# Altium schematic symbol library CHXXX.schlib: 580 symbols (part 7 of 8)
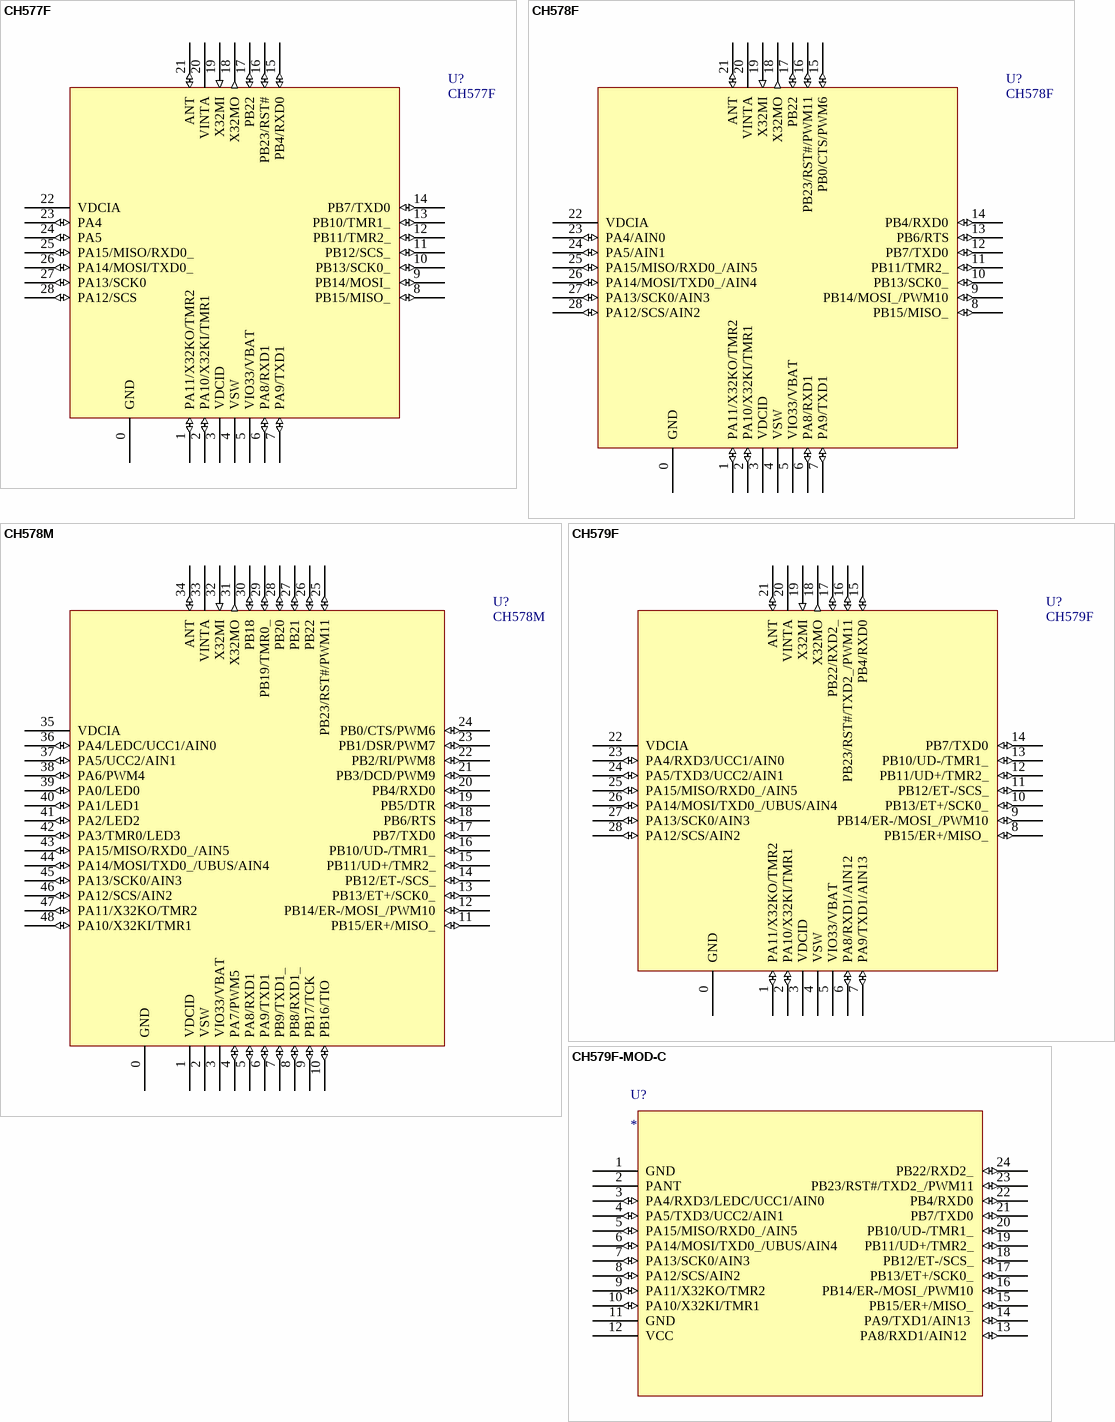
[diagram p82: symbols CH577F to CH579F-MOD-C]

## CH579F-MOD-C
designator U?
CH579F module, ARM M0 MCU with BLE+Ethernet+USB Host/Device
footprint BLEMOD-R2-1v0-24PIN
pins: 1 GND (power), 2 PANT, 3 PA4/RXD3/LEDC/UCC1/AIN0  (io), 4 PA5/TXD3/UCC2/AIN1   (io), 5 PA15/MISO/RXD0_/AIN5   (io), 6 PA14/MOSI/TXD0_/UBUS/AIN4 (io), 7 PA13/SCK0/AIN3   (io), 8 PA12/SCS/AIN2   (io), 9 PA11/X32KO/TMR2   (io), 10 PA10/X32KI/TMR1   (io), 11 GND (power), 12 VCC (power), 13 PA8/RXD1/AIN12   (io), 14 PA9/TXD1/AIN13  (io), 15 PB15/ER+/MISO_ (io), 16 PB14/ER-/MOSI_/PWM10 (io), 17 PB13/ET+/SCK0_ (io), 18 PB12/ET-/SCS_ (io), 19 PB11/UD+/TMR2_ (io), 20 PB10/UD-/TMR1_ (io), 21 PB7/TXD0 (io), 22 PB4/RXD0 (io), 23 PB23/RST#/TXD2_/PWM11 (io), 24 PB22/RXD2_ (io)

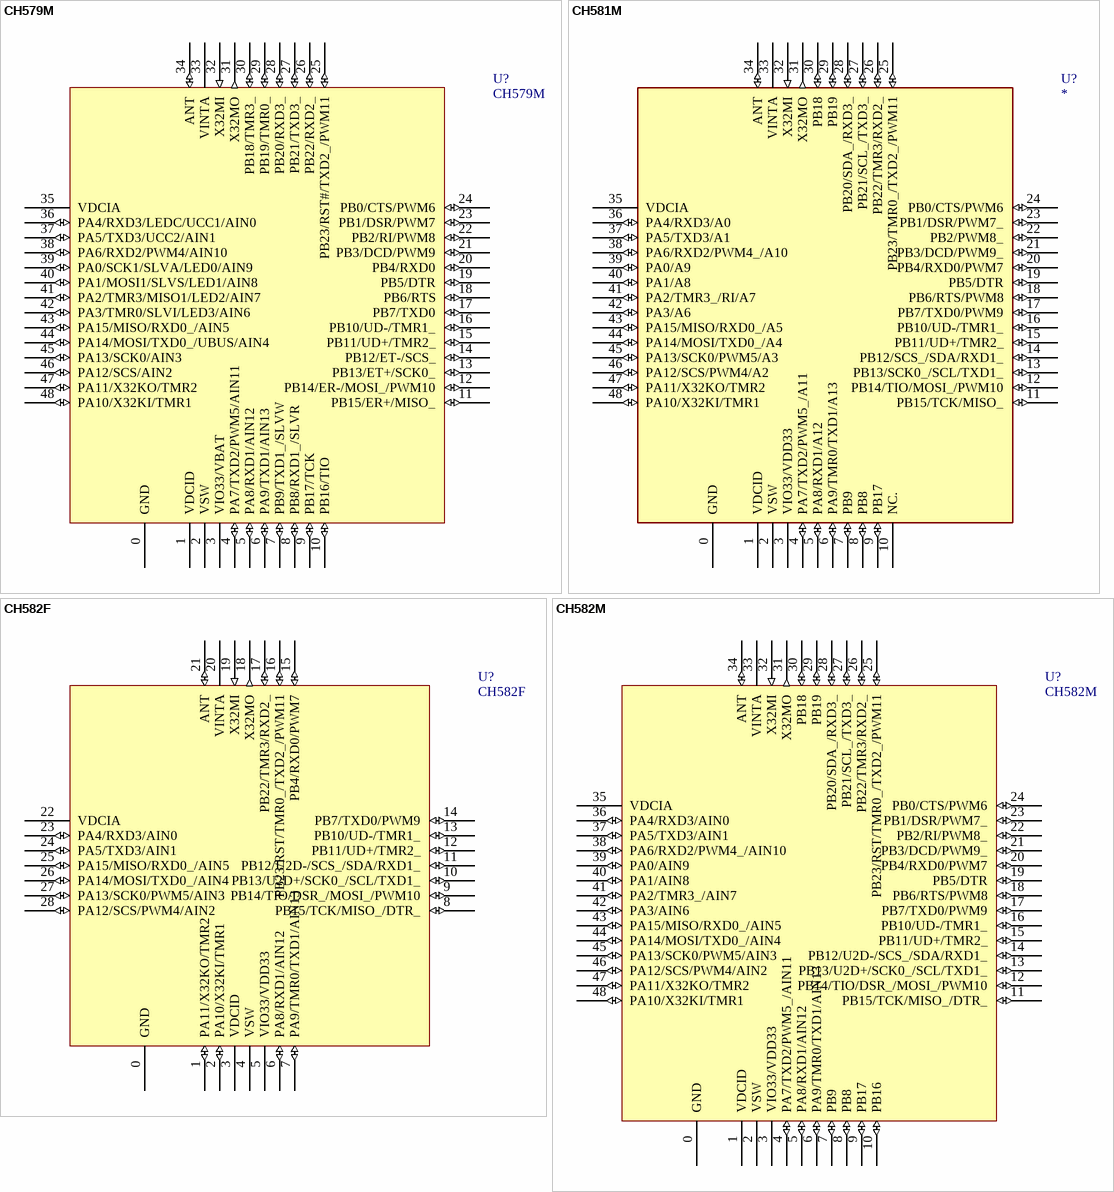
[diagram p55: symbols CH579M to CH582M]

## CH579M
designator U?
ARM M0 MCU with Bluetooth-LowEnergy+Ethernet+USB+segment-LCD
footprint QFN48_5X5
pins: 0 GND (power), 1 VDCID (power), 2 VSW (power), 3 VIO33/VBAT (power), 4 PA7/TXD2/PWM5/AIN11 (io), 5 PA8/RXD1/AIN12 (io), 6 PA9/TXD1/AIN13 (io), 7 PB9/TXD1_/SLVW (io), 8 PB8/RXD1_/SLVR (io), 9 PB17/TCK (io), 10 PB16/TIO (io), 11 PB15/ER+/MISO_ (io), 12 PB14/ER-/MOSI_/PWM10 (io), 13 PB13/ET+/SCK0_ (io), 14 PB12/ET-/SCS_ (io), 15 PB11/UD+/TMR2_ (io), 16 PB10/UD-/TMR1_ (io), 17 PB7/TXD0 (io), 18 PB6/RTS (io), 19 PB5/DTR (io), 20 PB4/RXD0 (io), 21 PB3/DCD/PWM9 (io), 22 PB2/RI/PWM8 (io), 23 PB1/DSR/PWM7 (io), 24 PB0/CTS/PWM6 (io), 25 PB23/RST#/TXD2_/PWM11 (io), 26 PB22/RXD2_ (io), 27 PB21/TXD3_ (io), 28 PB20/RXD3_ (io), 29 PB19/TMR0_ (io), 30 PB18/TMR3_ (io), 31 X32MO (out), 32 X32MI (in), 33 VINTA (power), 34 ANT (io), 35 VDCIA (power), 36 PA4/RXD3/LEDC/UCC1/AIN0 (io), 37 PA5/TXD3/UCC2/AIN1 (io), 38 PA6/RXD2/PWM4/AIN10 (io), 39 PA0/SCK1/SLVA/LED0/AIN9 (io), 40 PA1/MOSI1/SLVS/LED1/AIN8 (io), 41 PA2/TMR3/MISO1/LED2/AIN7 (io), 42 PA3/TMR0/SLVI/LED3/AIN6 (io), 43 PA15/MISO/RXD0_/AIN5 (io), 44 PA14/MOSI/TXD0_/UBUS/AIN4 (io), 45 PA13/SCK0/AIN3 (io), 46 PA12/SCS/AIN2 (io), 47 PA11/X32KO/TMR2 (io), 48 PA10/X32KI/TMR1 (io)

## CH581M
designator U?
RISC-V MCU with BLE/USB/ADC/PWM/SPI/I2C/4*UART
footprint QFN48_5X5
pins: 0 GND (power), 1 VDCID (power), 2 VSW (power), 3 VIO33/VDD33 (power), 4 PA7/TXD2/PWM5_/A11 (io), 5 PA8/RXD1/A12 (io), 6 PA9/TMR0/TXD1/A13 (io), 7 PB9 (io), 8 PB8 (io), 9 PB17 (io), 10 NC., 11 PB15/TCK/MISO_ (io), 12 PB14/TIO/MOSI_/PWM10 (io), 13 PB13/SCK0_/SCL/TXD1_ (io), 14 PB12/SCS_/SDA/RXD1_ (io), 15 PB11/UD+/TMR2_ (io), 16 PB10/UD-/TMR1_ (io), 17 PB7/TXD0/PWM9 (io), 18 PB6/RTS/PWM8 (io), 19 PB5/DTR (io), 20 PB4/RXD0/PWM7 (io), 21 PB3/DCD/PWM9_ (io), 22 PB2/PWM8_ (io), 23 PB1/DSR/PWM7_ (io), 24 PB0/CTS/PWM6 (io), 25 PB23/TMR0_/TXD2_/PWM11 (io), 26 PB22/TMR3/RXD2_ (io), 27 PB21/SCL_/TXD3_ (io), 28 PB20/SDA_/RXD3_ (io), 29 PB19 (io), 30 PB18 (io), 31 X32MO (out), 32 X32MI (in), 33 VINTA (power), 34 ANT (io), 35 VDCIA (power), 36 PA4/RXD3/A0 (io), 37 PA5/TXD3/A1 (io), 38 PA6/RXD2/PWM4_/A10 (io), 39 PA0/A9 (io), 40 PA1/A8 (io), 41 PA2/TMR3_/RI/A7 (io), 42 PA3/A6 (io), 43 PA15/MISO/RXD0_/A5 (io), 44 PA14/MOSI/TXD0_/A4 (io), 45 PA13/SCK0/PWM5/A3 (io), 46 PA12/SCS/PWM4/A2 (io), 47 PA11/X32KO/TMR2 (io), 48 PA10/X32KI/TMR1 (io)

## CH582F
designator U?
RISC-V MCU with BLE/2*USB/ADC/PWM/SPI/I2C/4*UART
footprint QFN28_4X4
pins: 0 GND (power), 1 PA11/X32KO/TMR2 (io), 2 PA10/X32KI/TMR1 (io), 3 VDCID (power), 4 VSW (power), 5 VIO33/VDD33 (power), 6 PA8/RXD1/AIN12 (io), 7 PA9/TMR0/TXD1/AIN13 (io), 8 PB15/TCK/MISO_/DTR_ (io), 9 PB14/TIO/DSR_/MOSI_/PWM10 (io), 10 PB13/U2D+/SCK0_/SCL/TXD1_ (io), 11 PB12/U2D-/SCS_/SDA/RXD1_ (io), 12 PB11/UD+/TMR2_ (io), 13 PB10/UD-/TMR1_ (io), 14 PB7/TXD0/PWM9 (io), 15 PB4/RXD0/PWM7 (io), 16 PB23/RST/TMR0_/TXD2_/PWM11 (io), 17 PB22/TMR3/RXD2_ (io), 18 X32MO (out), 19 X32MI (in), 20 VINTA (power), 21 ANT (io), 22 VDCIA (power), 23 PA4/RXD3/AIN0 (io), 24 PA5/TXD3/AIN1 (io), 25 PA15/MISO/RXD0_/AIN5 (io), 26 PA14/MOSI/TXD0_/AIN4 (io), 27 PA13/SCK0/PWM5/AIN3 (io), 28 PA12/SCS/PWM4/AIN2 (io)

## CH582M
designator U?
RISC-V MCU with BLE/2*USB/ADC/PWM/SPI/I2C/4*UART
footprint QFN48_5X5
pins: 0 GND (power), 1 VDCID (power), 2 VSW (power), 3 VIO33/VDD33 (power), 4 PA7/TXD2/PWM5_/AIN11 (io), 5 PA8/RXD1/AIN12 (io), 6 PA9/TMR0/TXD1/AIN13 (io), 7 PB9 (io), 8 PB8 (io), 9 PB17 (io), 10 PB16 (io), 11 PB15/TCK/MISO_/DTR_ (io), 12 PB14/TIO/DSR_/MOSI_/PWM10 (io), 13 PB13/U2D+/SCK0_/SCL/TXD1_ (io), 14 PB12/U2D-/SCS_/SDA/RXD1_ (io), 15 PB11/UD+/TMR2_ (io), 16 PB10/UD-/TMR1_ (io), 17 PB7/TXD0/PWM9 (io), 18 PB6/RTS/PWM8 (io), 19 PB5/DTR (io), 20 PB4/RXD0/PWM7 (io), 21 PB3/DCD/PWM9_ (io), 22 PB2/RI/PWM8_ (io), 23 PB1/DSR/PWM7_ (io), 24 PB0/CTS/PWM6 (io), 25 PB23/RST/TMR0_/TXD2_/PWM11 (io), 26 PB22/TMR3/RXD2_ (io), 27 PB21/SCL_/TXD3_ (io), 28 PB20/SDA_/RXD3_ (io), 29 PB19 (io), 30 PB18 (io), 31 X32MO (out), 32 X32MI (in), 33 VINTA (power), 34 ANT (io), 35 VDCIA (power), 36 PA4/RXD3/AIN0 (io), 37 PA5/TXD3/AIN1 (io), 38 PA6/RXD2/PWM4_/AIN10 (io), 39 PA0/AIN9 (io), 40 PA1/AIN8 (io), 41 PA2/TMR3_/AIN7 (io), 42 PA3/AIN6 (io), 43 PA15/MISO/RXD0_/AIN5 (io), 44 PA14/MOSI/TXD0_/AIN4 (io), 45 PA13/SCK0/PWM5/AIN3 (io), 46 PA12/SCS/PWM4/AIN2 (io), 47 PA11/X32KO/TMR2 (io), 48 PA10/X32KI/TMR1 (io)

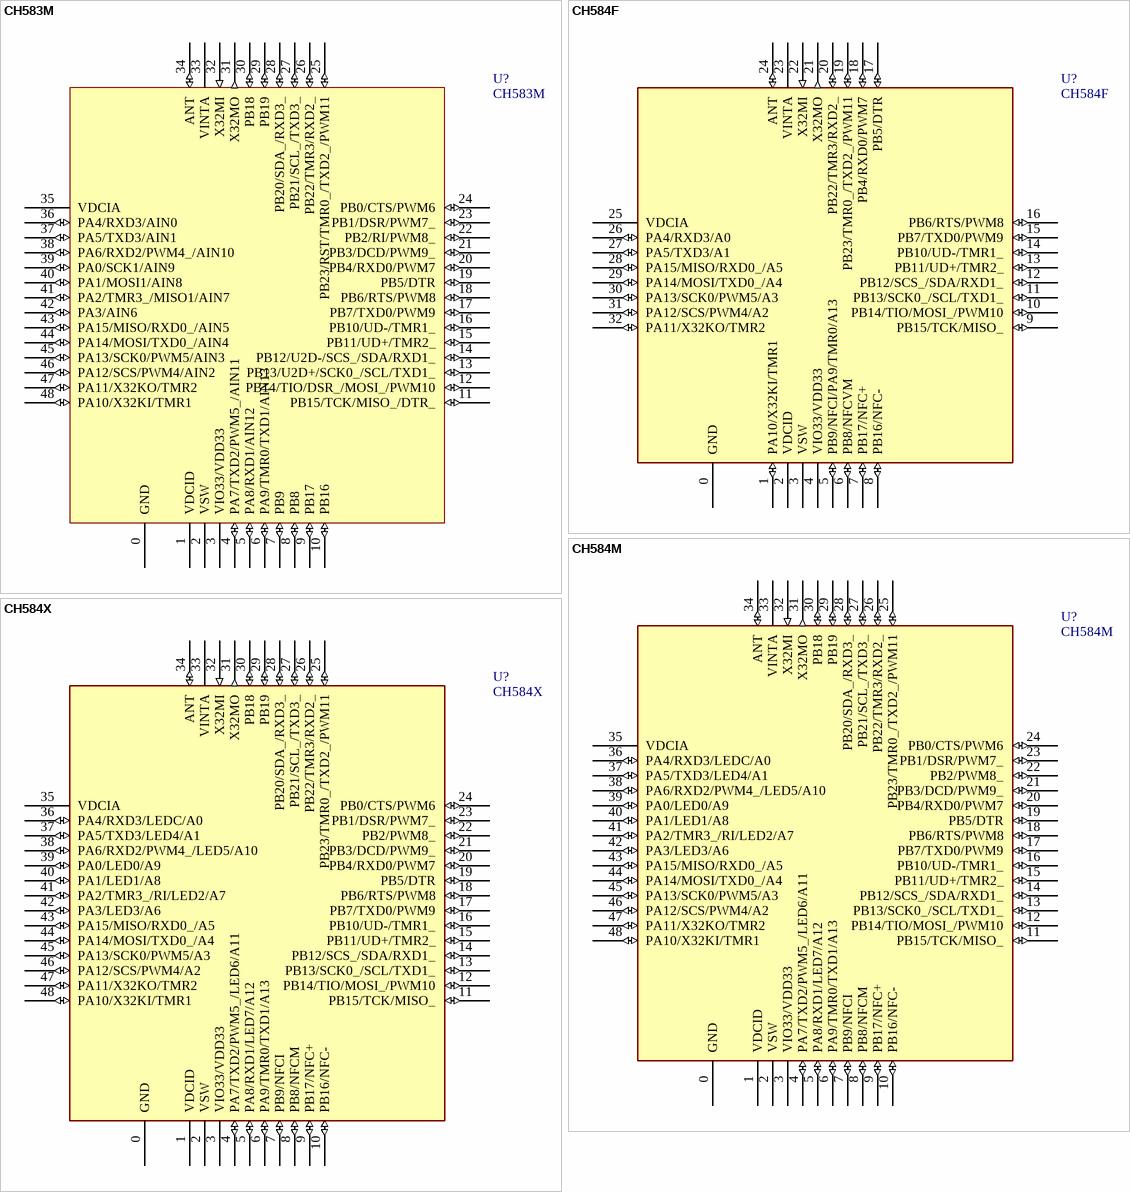
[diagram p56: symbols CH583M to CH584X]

## CH583M
designator U?
RISC-V MCU with BLE/2*USB/ADC/PWM/SPI/I2C/4*UART
footprint QFN48_5X5
pins: 0 GND (power), 1 VDCID (power), 2 VSW (power), 3 VIO33/VDD33 (power), 4 PA7/TXD2/PWM5_/AIN11 (io), 5 PA8/RXD1/AIN12 (io), 6 PA9/TMR0/TXD1/AIN13 (io), 7 PB9 (io), 8 PB8 (io), 9 PB17 (io), 10 PB16 (io), 11 PB15/TCK/MISO_/DTR_ (io), 12 PB14/TIO/DSR_/MOSI_/PWM10 (io), 13 PB13/U2D+/SCK0_/SCL/TXD1_ (io), 14 PB12/U2D-/SCS_/SDA/RXD1_ (io), 15 PB11/UD+/TMR2_ (io), 16 PB10/UD-/TMR1_ (io), 17 PB7/TXD0/PWM9 (io), 18 PB6/RTS/PWM8 (io), 19 PB5/DTR (io), 20 PB4/RXD0/PWM7 (io), 21 PB3/DCD/PWM9_ (io), 22 PB2/RI/PWM8_ (io), 23 PB1/DSR/PWM7_ (io), 24 PB0/CTS/PWM6 (io), 25 PB23/RST/TMR0_/TXD2_/PWM11 (io), 26 PB22/TMR3/RXD2_ (io), 27 PB21/SCL_/TXD3_ (io), 28 PB20/SDA_/RXD3_ (io), 29 PB19 (io), 30 PB18 (io), 31 X32MO (out), 32 X32MI (in), 33 VINTA (power), 34 ANT (io), 35 VDCIA (power), 36 PA4/RXD3/AIN0 (io), 37 PA5/TXD3/AIN1 (io), 38 PA6/RXD2/PWM4_/AIN10 (io), 39 PA0/SCK1/AIN9 (io), 40 PA1/MOSI1/AIN8 (io), 41 PA2/TMR3_/MISO1/AIN7 (io), 42 PA3/AIN6 (io), 43 PA15/MISO/RXD0_/AIN5 (io), 44 PA14/MOSI/TXD0_/AIN4 (io), 45 PA13/SCK0/PWM5/AIN3 (io), 46 PA12/SCS/PWM4/AIN2 (io), 47 PA11/X32KO/TMR2 (io), 48 PA10/X32KI/TMR1 (io)

## CH584F
designator U?
RISC-V MCU with BLE/USB/NFC/ADC/PWM/SPI/I2C/4*UART/LCD
footprint QFN32_4X4
pins: 0 GND (power), 1 PA10/X32KI/TMR1 (io), 2 VDCID (power), 3 VSW (power), 4 VIO33/VDD33 (power), 5 PB9/NFCI/PA9/TMR0/A13 (io), 6 PB8/NFCVM (io), 7 PB17/NFC+ (io), 8 PB16/NFC- (io), 9 PB15/TCK/MISO_ (io), 10 PB14/TIO/MOSI_/PWM10 (io), 11 PB13/SCK0_/SCL/TXD1_ (io), 12 PB12/SCS_/SDA/RXD1_ (io), 13 PB11/UD+/TMR2_ (io), 14 PB10/UD-/TMR1_ (io), 15 PB7/TXD0/PWM9 (io), 16 PB6/RTS/PWM8 (io), 17 PB5/DTR (io), 18 PB4/RXD0/PWM7 (io), 19 PB23/TMR0_/TXD2_/PWM11 (io), 20 PB22/TMR3/RXD2_ (io), 21 X32MO (out), 22 X32MI (in), 23 VINTA (power), 24 ANT (io), 25 VDCIA (power), 26 PA4/RXD3/A0 (io), 27 PA5/TXD3/A1 (io), 28 PA15/MISO/RXD0_/A5 (io), 29 PA14/MOSI/TXD0_/A4 (io), 30 PA13/SCK0/PWM5/A3 (io), 31 PA12/SCS/PWM4/A2 (io), 32 PA11/X32KO/TMR2 (io)

## CH584M
designator U?
RISC-V MCU with BLE/USB/NFC/ADC/PWM/SPI/I2C/4*UART/LCD
footprint QFN48_5X5
pins: 0 GND (power), 1 VDCID (power), 2 VSW (power), 3 VIO33/VDD33 (power), 4 PA7/TXD2/PWM5_/LED6/A11 (io), 5 PA8/RXD1/LED7/A12 (io), 6 PA9/TMR0/TXD1/A13 (io), 7 PB9/NFCI (io), 8 PB8/NFCM (io), 9 PB17/NFC+ (io), 10 PB16/NFC- (io), 11 PB15/TCK/MISO_ (io), 12 PB14/TIO/MOSI_/PWM10 (io), 13 PB13/SCK0_/SCL/TXD1_ (io), 14 PB12/SCS_/SDA/RXD1_ (io), 15 PB11/UD+/TMR2_ (io), 16 PB10/UD-/TMR1_ (io), 17 PB7/TXD0/PWM9 (io), 18 PB6/RTS/PWM8 (io), 19 PB5/DTR (io), 20 PB4/RXD0/PWM7 (io), 21 PB3/DCD/PWM9_ (io), 22 PB2/PWM8_ (io), 23 PB1/DSR/PWM7_ (io), 24 PB0/CTS/PWM6 (io), 25 PB23/TMR0_/TXD2_/PWM11 (io), 26 PB22/TMR3/RXD2_ (io), 27 PB21/SCL_/TXD3_ (io), 28 PB20/SDA_/RXD3_ (io), 29 PB19 (io), 30 PB18 (io), 31 X32MO (out), 32 X32MI (in), 33 VINTA (power), 34 ANT (io), 35 VDCIA (power), 36 PA4/RXD3/LEDC/A0 (io), 37 PA5/TXD3/LED4/A1 (io), 38 PA6/RXD2/PWM4_/LED5/A10 (io), 39 PA0/LED0/A9 (io), 40 PA1/LED1/A8 (io), 41 PA2/TMR3_/RI/LED2/A7 (io), 42 PA3/LED3/A6 (io), 43 PA15/MISO/RXD0_/A5 (io), 44 PA14/MOSI/TXD0_/A4 (io), 45 PA13/SCK0/PWM5/A3 (io), 46 PA12/SCS/PWM4/A2 (io), 47 PA11/X32KO/TMR2 (io), 48 PA10/X32KI/TMR1 (io)

## CH584X
designator U?
RISC-V MCU with BLE/USB/NFC/ADC/PWM/SPI/I2C/4*UART/LCD
footprint QFN48_5X5
pins: 0 GND (power), 1 VDCID (power), 2 VSW (power), 3 VIO33/VDD33 (power), 4 PA7/TXD2/PWM5_/LED6/A11 (io), 5 PA8/RXD1/LED7/A12 (io), 6 PA9/TMR0/TXD1/A13 (io), 7 PB9/NFCI (io), 8 PB8/NFCM (io), 9 PB17/NFC+ (io), 10 PB16/NFC- (io), 11 PB15/TCK/MISO_ (io), 12 PB14/TIO/MOSI_/PWM10 (io), 13 PB13/SCK0_/SCL/TXD1_ (io), 14 PB12/SCS_/SDA/RXD1_ (io), 15 PB11/UD+/TMR2_ (io), 16 PB10/UD-/TMR1_ (io), 17 PB7/TXD0/PWM9 (io), 18 PB6/RTS/PWM8 (io), 19 PB5/DTR (io), 20 PB4/RXD0/PWM7 (io), 21 PB3/DCD/PWM9_ (io), 22 PB2/PWM8_ (io), 23 PB1/DSR/PWM7_ (io), 24 PB0/CTS/PWM6 (io), 25 PB23/TMR0_/TXD2_/PWM11 (io), 26 PB22/TMR3/RXD2_ (io), 27 PB21/SCL_/TXD3_ (io), 28 PB20/SDA_/RXD3_ (io), 29 PB19 (io), 30 PB18 (io), 31 X32MO (out), 32 X32MI (in), 33 VINTA (power), 34 ANT (io), 35 VDCIA (power), 36 PA4/RXD3/LEDC/A0 (io), 37 PA5/TXD3/LED4/A1 (io), 38 PA6/RXD2/PWM4_/LED5/A10 (io), 39 PA0/LED0/A9 (io), 40 PA1/LED1/A8 (io), 41 PA2/TMR3_/RI/LED2/A7 (io), 42 PA3/LED3/A6 (io), 43 PA15/MISO/RXD0_/A5 (io), 44 PA14/MOSI/TXD0_/A4 (io), 45 PA13/SCK0/PWM5/A3 (io), 46 PA12/SCS/PWM4/A2 (io), 47 PA11/X32KO/TMR2 (io), 48 PA10/X32KI/TMR1 (io)

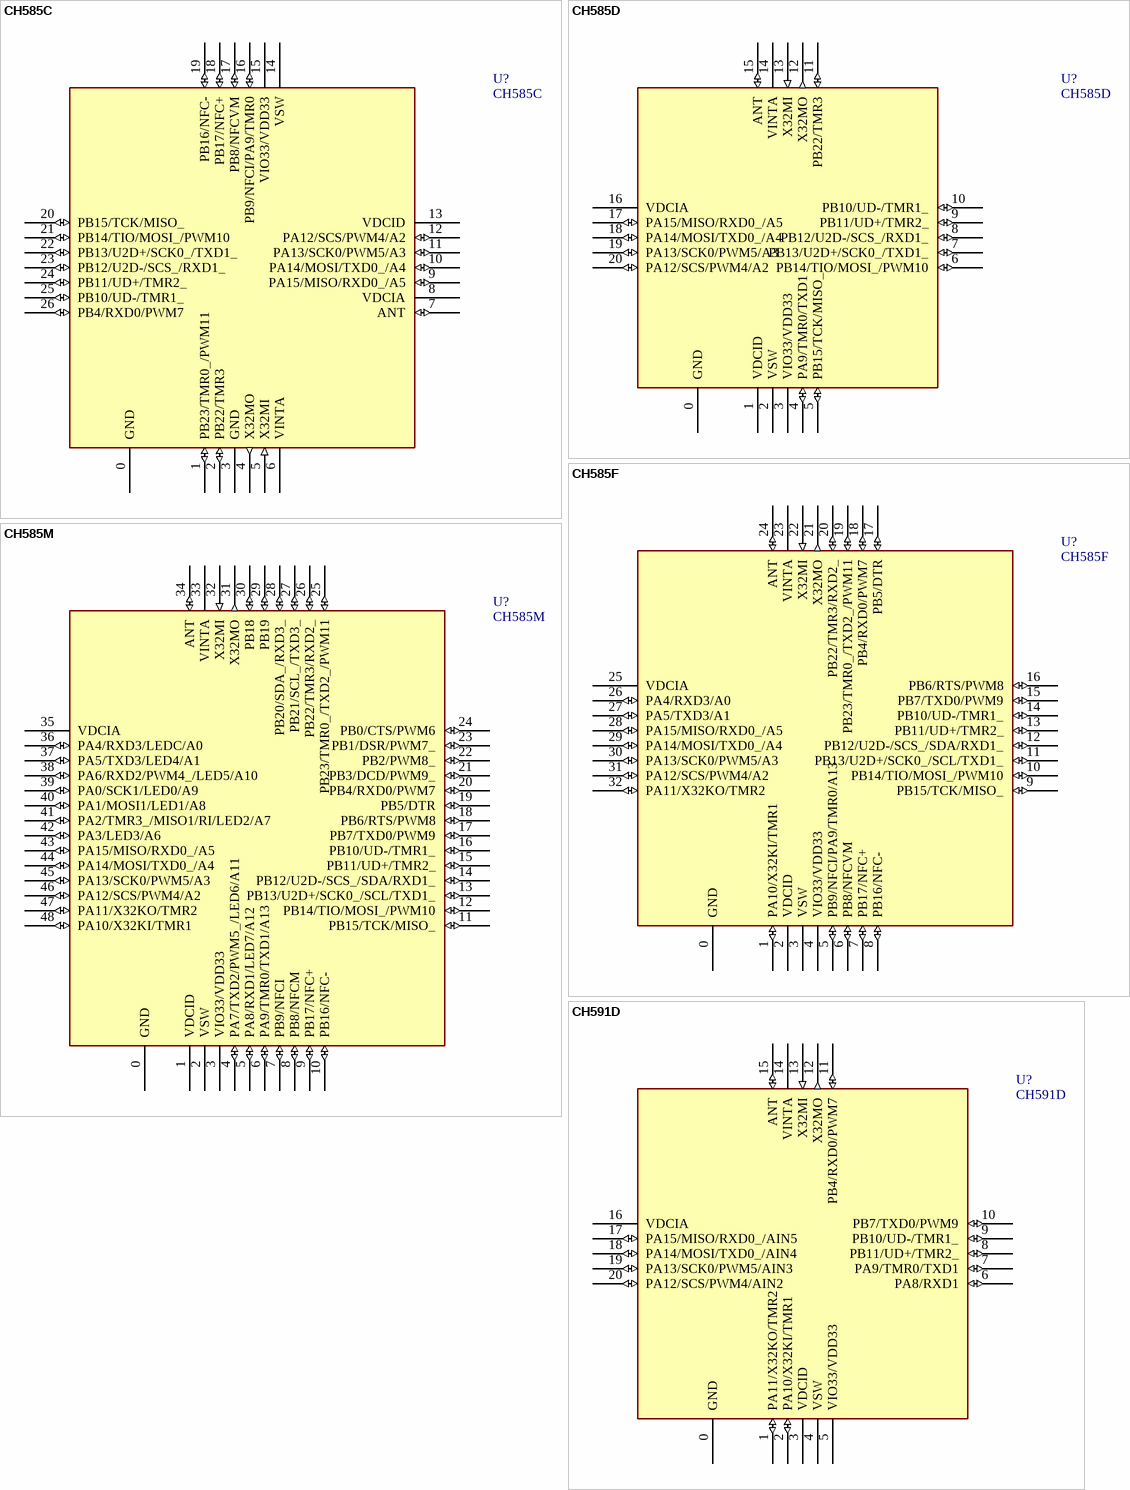
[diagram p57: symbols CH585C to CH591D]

## CH585C
designator U?
RISC-V MCU with BLE/HSUSB/USB/NFC/ADC/PWM/SPI/2*UART
footprint QFN26C_3X3
pins: 0 GND (power), 1 PB23/TMR0_/PWM11 (io), 2 PB22/TMR3 (io), 3 GND (power), 4 X32MO (out), 5 X32MI (in), 6 VINTA (power), 7 ANT (io), 8 VDCIA (power), 9 PA15/MISO/RXD0_/A5 (io), 10 PA14/MOSI/TXD0_/A4 (io), 11 PA13/SCK0/PWM5/A3 (io), 12 PA12/SCS/PWM4/A2 (io), 13 VDCID (power), 14 VSW (power), 15 VIO33/VDD33 (power), 16 PB9/NFCI/PA9/TMR0 (io), 17 PB8/NFCVM (io), 18 PB17/NFC+ (io), 19 PB16/NFC- (io), 20 PB15/TCK/MISO_ (io), 21 PB14/TIO/MOSI_/PWM10 (io), 22 PB13/U2D+/SCK0_/TXD1_ (io), 23 PB12/U2D-/SCS_/RXD1_ (io), 24 PB11/UD+/TMR2_ (io), 25 PB10/UD-/TMR1_ (io), 26 PB4/RXD0/PWM7 (io)

## CH585D
designator U?
RISC-V MCU with BLE/HSUSB/USB/ADC/PWM/SPI/2*UART
footprint QFN20_3X3 (Footprint not found)
pins: 0 GND (power), 1 VDCID (power), 2 VSW (power), 3 VIO33/VDD33 (power), 4 PA9/TMR0/TXD1 (io), 5 PB15/TCK/MISO_ (io), 6 PB14/TIO/MOSI_/PWM10 (io), 7 PB13/U2D+/SCK0_/TXD1_ (io), 8 PB12/U2D-/SCS_/RXD1_ (io), 9 PB11/UD+/TMR2_ (io), 10 PB10/UD-/TMR1_ (io), 11 PB22/TMR3 (io), 12 X32MO (out), 13 X32MI (in), 14 VINTA (power), 15 ANT (io), 16 VDCIA (power), 17 PA15/MISO/RXD0_/A5 (io), 18 PA14/MOSI/TXD0_/A4 (io), 19 PA13/SCK0/PWM5/A3 (io), 20 PA12/SCS/PWM4/A2 (io)

## CH585F
designator U?
RISC-V MCU with BLE/HSUSB/USB/NFC/ADC/PWM/SPI/I2C/4*UART/LCD
footprint QFN32_4X4
pins: 0 GND (power), 1 PA10/X32KI/TMR1 (io), 2 VDCID (power), 3 VSW (power), 4 VIO33/VDD33 (power), 5 PB9/NFCI/PA9/TMR0/A13 (io), 6 PB8/NFCVM (io), 7 PB17/NFC+ (io), 8 PB16/NFC- (io), 9 PB15/TCK/MISO_ (io), 10 PB14/TIO/MOSI_/PWM10 (io), 11 PB13/U2D+/SCK0_/SCL/TXD1_ (io), 12 PB12/U2D-/SCS_/SDA/RXD1_ (io), 13 PB11/UD+/TMR2_ (io), 14 PB10/UD-/TMR1_ (io), 15 PB7/TXD0/PWM9 (io), 16 PB6/RTS/PWM8 (io), 17 PB5/DTR (io), 18 PB4/RXD0/PWM7 (io), 19 PB23/TMR0_/TXD2_/PWM11 (io), 20 PB22/TMR3/RXD2_ (io), 21 X32MO (out), 22 X32MI (in), 23 VINTA (power), 24 ANT (io), 25 VDCIA (power), 26 PA4/RXD3/A0 (io), 27 PA5/TXD3/A1 (io), 28 PA15/MISO/RXD0_/A5 (io), 29 PA14/MOSI/TXD0_/A4 (io), 30 PA13/SCK0/PWM5/A3 (io), 31 PA12/SCS/PWM4/A2 (io), 32 PA11/X32KO/TMR2 (io)

## CH585M
designator U?
RISC-V MCU with BLE/HSUSB/USB/NFC/ADC/PWM/2*SPI/I2C/4*UART/LCD
footprint QFN48_5X5
pins: 0 GND (power), 1 VDCID (power), 2 VSW (power), 3 VIO33/VDD33 (power), 4 PA7/TXD2/PWM5_/LED6/A11 (io), 5 PA8/RXD1/LED7/A12 (io), 6 PA9/TMR0/TXD1/A13 (io), 7 PB9/NFCI (io), 8 PB8/NFCM (io), 9 PB17/NFC+ (io), 10 PB16/NFC- (io), 11 PB15/TCK/MISO_ (io), 12 PB14/TIO/MOSI_/PWM10 (io), 13 PB13/U2D+/SCK0_/SCL/TXD1_ (io), 14 PB12/U2D-/SCS_/SDA/RXD1_ (io), 15 PB11/UD+/TMR2_ (io), 16 PB10/UD-/TMR1_ (io), 17 PB7/TXD0/PWM9 (io), 18 PB6/RTS/PWM8 (io), 19 PB5/DTR (io), 20 PB4/RXD0/PWM7 (io), 21 PB3/DCD/PWM9_ (io), 22 PB2/PWM8_ (io), 23 PB1/DSR/PWM7_ (io), 24 PB0/CTS/PWM6 (io), 25 PB23/TMR0_/TXD2_/PWM11 (io), 26 PB22/TMR3/RXD2_ (io), 27 PB21/SCL_/TXD3_ (io), 28 PB20/SDA_/RXD3_ (io), 29 PB19 (io), 30 PB18 (io), 31 X32MO (out), 32 X32MI (in), 33 VINTA (power), 34 ANT (io), 35 VDCIA (power), 36 PA4/RXD3/LEDC/A0 (io), 37 PA5/TXD3/LED4/A1 (io), 38 PA6/RXD2/PWM4_/LED5/A10 (io), 39 PA0/SCK1/LED0/A9 (io), 40 PA1/MOSI1/LED1/A8 (io), 41 PA2/TMR3_/MISO1/RI/LED2/A7 (io), 42 PA3/LED3/A6 (io), 43 PA15/MISO/RXD0_/A5 (io), 44 PA14/MOSI/TXD0_/A4 (io), 45 PA13/SCK0/PWM5/A3 (io), 46 PA12/SCS/PWM4/A2 (io), 47 PA11/X32KO/TMR2 (io), 48 PA10/X32KI/TMR1 (io)

## CH591D
designator U?
RISC-V MCU with BLE/USB/ADC/SPI/2*UART
footprint QFN20_3X3
pins: 0 GND (power), 1 PA11/X32KO/TMR2 (io), 2 PA10/X32KI/TMR1 (io), 3 VDCID (power), 4 VSW (power), 5 VIO33/VDD33 (power), 6 PA8/RXD1 (io), 7 PA9/TMR0/TXD1 (io), 8 PB11/UD+/TMR2_ (io), 9 PB10/UD-/TMR1_ (io), 10 PB7/TXD0/PWM9 (io), 11 PB4/RXD0/PWM7 (io), 12 X32MO (out), 13 X32MI (in), 14 VINTA (power), 15 ANT (io), 16 VDCIA (power), 17 PA15/MISO/RXD0_/AIN5 (io), 18 PA14/MOSI/TXD0_/AIN4 (io), 19 PA13/SCK0/PWM5/AIN3 (io), 20 PA12/SCS/PWM4/AIN2 (io)

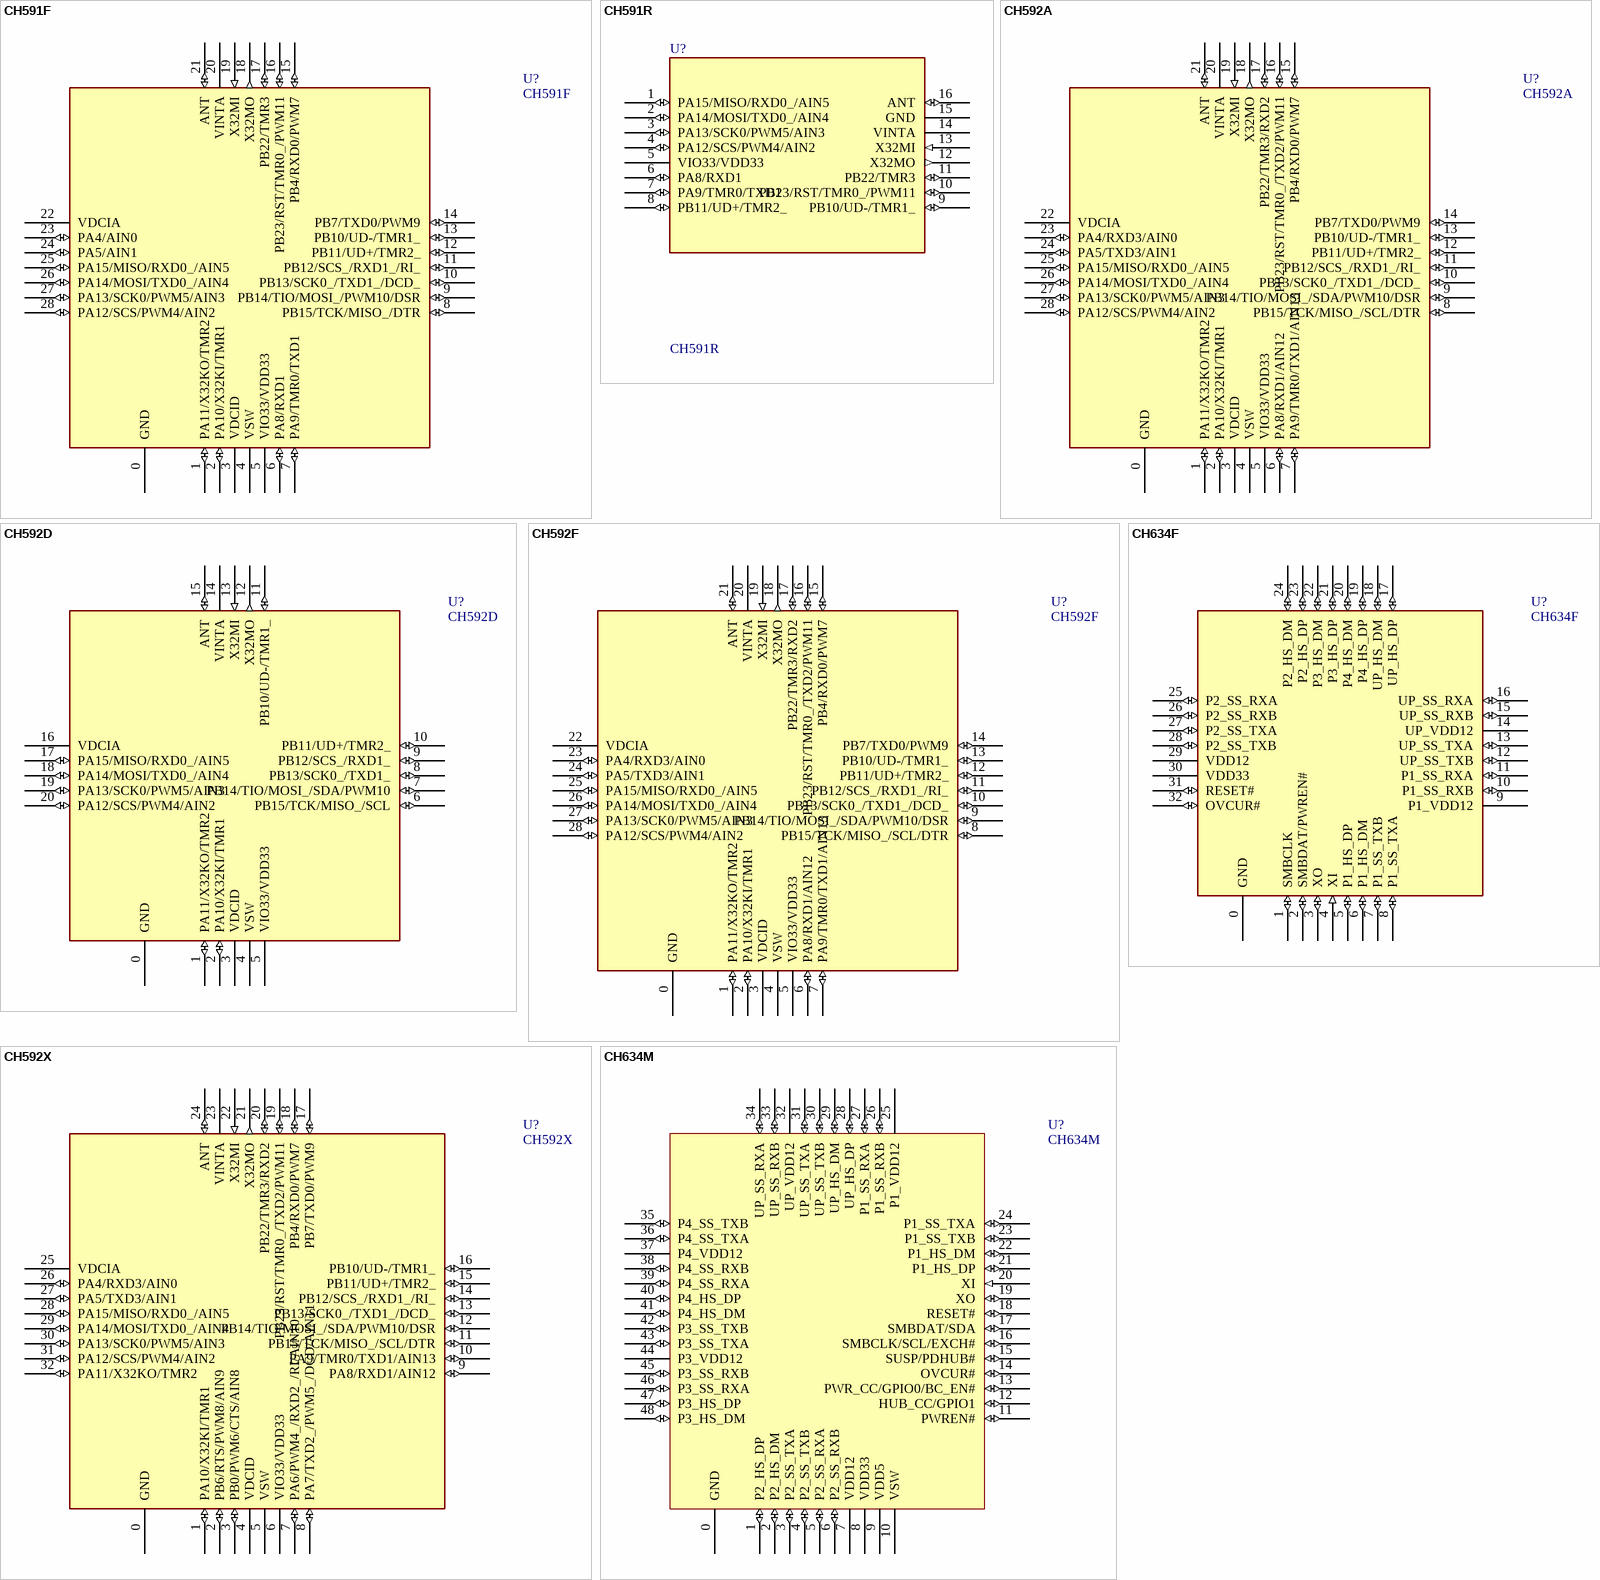
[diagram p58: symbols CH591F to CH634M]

## CH591F
designator U?
RISC-V MCU with BLE/USB/ADC/SPI/2*UART/LCD
footprint QFN28_4X4 (Footprint not found)
pins: 0 GND (power), 1 PA11/X32KO/TMR2 (io), 2 PA10/X32KI/TMR1 (io), 3 VDCID (power), 4 VSW (power), 5 VIO33/VDD33 (power), 6 PA8/RXD1 (io), 7 PA9/TMR0/TXD1 (io), 8 PB15/TCK/MISO_/DTR (io), 9 PB14/TIO/MOSI_/PWM10/DSR (io), 10 PB13/SCK0_/TXD1_/DCD_ (io), 11 PB12/SCS_/RXD1_/RI_ (io), 12 PB11/UD+/TMR2_ (io), 13 PB10/UD-/TMR1_ (io), 14 PB7/TXD0/PWM9 (io), 15 PB4/RXD0/PWM7 (io), 16 PB23/RST/TMR0_/PWM11 (io), 17 PB22/TMR3 (io), 18 X32MO (out), 19 X32MI (in), 20 VINTA (power), 21 ANT (io), 22 VDCIA (power), 23 PA4/AIN0 (io), 24 PA5/AIN1 (io), 25 PA15/MISO/RXD0_/AIN5 (io), 26 PA14/MOSI/TXD0_/AIN4 (io), 27 PA13/SCK0/PWM5/AIN3 (io), 28 PA12/SCS/PWM4/AIN2 (io)

## CH591R
designator U?
RISC-V MCU with BLE/USB/ADC/SPI/2*UART
footprint TSSOP16 (Footprint not found)
pins: 1 PA15/MISO/RXD0_/AIN5 (io), 2 PA14/MOSI/TXD0_/AIN4 (io), 3 PA13/SCK0/PWM5/AIN3 (io), 4 PA12/SCS/PWM4/AIN2 (io), 5 VIO33/VDD33 (power), 6 PA8/RXD1 (io), 7 PA9/TMR0/TXD1 (io), 8 PB11/UD+/TMR2_ (io), 9 PB10/UD-/TMR1_ (io), 10 PB23/RST/TMR0_/PWM11 (io), 11 PB22/TMR3 (io), 12 X32MO (out), 13 X32MI (in), 14 VINTA (power), 15 GND (power), 16 ANT (io)

## CH592A
designator U?
RISC-V MCU with BLE/USB/ADC/SPI/4*UART/I2C/LCD
footprint QFN28_4X4 (Footprint not found)
pins: 0 GND (power), 1 PA11/X32KO/TMR2 (io), 2 PA10/X32KI/TMR1 (io), 3 VDCID (power), 4 VSW (power), 5 VIO33/VDD33 (power), 6 PA8/RXD1/AIN12 (io), 7 PA9/TMR0/TXD1/AIN13 (io), 8 PB15/TCK/MISO_/SCL/DTR (io), 9 PB14/TIO/MOSI_/SDA/PWM10/DSR (io), 10 PB13/SCK0_/TXD1_/DCD_ (io), 11 PB12/SCS_/RXD1_/RI_ (io), 12 PB11/UD+/TMR2_ (io), 13 PB10/UD-/TMR1_ (io), 14 PB7/TXD0/PWM9 (io), 15 PB4/RXD0/PWM7 (io), 16 PB23/RST/TMR0_/TXD2/PWM11 (io), 17 PB22/TMR3/RXD2 (io), 18 X32MO (out), 19 X32MI (in), 20 VINTA (power), 21 ANT (io), 22 VDCIA (power), 23 PA4/RXD3/AIN0 (io), 24 PA5/TXD3/AIN1 (io), 25 PA15/MISO/RXD0_/AIN5 (io), 26 PA14/MOSI/TXD0_/AIN4 (io), 27 PA13/SCK0/PWM5/AIN3 (io), 28 PA12/SCS/PWM4/AIN2 (io)

## CH592D
designator U?
RISC-V MCU with BLE/USB/ADC/SPI/2*UART/I2C
footprint QFN20_3X3
pins: 0 GND (power), 1 PA11/X32KO/TMR2 (io), 2 PA10/X32KI/TMR1 (io), 3 VDCID (power), 4 VSW (power), 5 VIO33/VDD33 (power), 6 PB15/TCK/MISO_/SCL (io), 7 PB14/TIO/MOSI_/SDA/PWM10 (io), 8 PB13/SCK0_/TXD1_ (io), 9 PB12/SCS_/RXD1_ (io), 10 PB11/UD+/TMR2_ (io), 11 PB10/UD-/TMR1_ (io), 12 X32MO (out), 13 X32MI (in), 14 VINTA (power), 15 ANT (io), 16 VDCIA (power), 17 PA15/MISO/RXD0_/AIN5 (io), 18 PA14/MOSI/TXD0_/AIN4 (io), 19 PA13/SCK0/PWM5/AIN3 (io), 20 PA12/SCS/PWM4/AIN2 (io)

## CH592F
designator U?
RISC-V MCU with BLE/USB/ADC/SPI/4*UART/I2C/LCD
footprint QFN28_4X4 (Footprint not found)
pins: 0 GND (power), 1 PA11/X32KO/TMR2 (io), 2 PA10/X32KI/TMR1 (io), 3 VDCID (power), 4 VSW (power), 5 VIO33/VDD33 (power), 6 PA8/RXD1/AIN12 (io), 7 PA9/TMR0/TXD1/AIN13 (io), 8 PB15/TCK/MISO_/SCL/DTR (io), 9 PB14/TIO/MOSI_/SDA/PWM10/DSR (io), 10 PB13/SCK0_/TXD1_/DCD_ (io), 11 PB12/SCS_/RXD1_/RI_ (io), 12 PB11/UD+/TMR2_ (io), 13 PB10/UD-/TMR1_ (io), 14 PB7/TXD0/PWM9 (io), 15 PB4/RXD0/PWM7 (io), 16 PB23/RST/TMR0_/TXD2/PWM11 (io), 17 PB22/TMR3/RXD2 (io), 18 X32MO (out), 19 X32MI (in), 20 VINTA (power), 21 ANT (io), 22 VDCIA (power), 23 PA4/RXD3/AIN0 (io), 24 PA5/TXD3/AIN1 (io), 25 PA15/MISO/RXD0_/AIN5 (io), 26 PA14/MOSI/TXD0_/AIN4 (io), 27 PA13/SCK0/PWM5/AIN3 (io), 28 PA12/SCS/PWM4/AIN2 (io)

## CH592X
designator U?
RISC-V MCU with BLE/USB/ADC/SPI/4*UART/I2C/LCD
footprint QFN32_4X4
pins: 0 GND (power), 1 PA10/X32KI/TMR1 (io), 2 PB6/RTS/PWM8/AIN9 (io), 3 PB0/PWM6/CTS/AIN8 (io), 4 VDCID (power), 5 VSW (power), 6 VIO33/VDD33 (power), 7 PA6/PWM4_/RXD2_/RI/AIN10 (io), 8 PA7/TXD2_/PWM5_/DCD/AIN11 (io), 9 PA8/RXD1/AIN12 (io), 10 PA9/TMR0/TXD1/AIN13 (io), 11 PB15/TCK/MISO_/SCL/DTR (io), 12 PB14/TIO/MOSI_/SDA/PWM10/DSR (io), 13 PB13/SCK0_/TXD1_/DCD_ (io), 14 PB12/SCS_/RXD1_/RI_ (io), 15 PB11/UD+/TMR2_ (io), 16 PB10/UD-/TMR1_ (io), 17 PB7/TXD0/PWM9 (io), 18 PB4/RXD0/PWM7 (io), 19 PB23/RST/TMR0_/TXD2/PWM11 (io), 20 PB22/TMR3/RXD2 (io), 21 X32MO (out), 22 X32MI (in), 23 VINTA (power), 24 ANT (io), 25 VDCIA (power), 26 PA4/RXD3/AIN0 (io), 27 PA5/TXD3/AIN1 (io), 28 PA15/MISO/RXD0_/AIN5 (io), 29 PA14/MOSI/TXD0_/AIN4 (io), 30 PA13/SCK0/PWM5/AIN3 (io), 31 PA12/SCS/PWM4/AIN2 (io), 32 PA11/X32KO/TMR2 (io)

## CH634F
designator U?
2 ports USB 3.0 SS hub + 2 ports USB 2.0 HS hub
footprint QFN32_4X4
pins: 0 GND (power), 1 SMBCLK (io), 2 SMBDAT/PWREN# (io), 3 XO (io), 4 XI (in), 5 P1_HS_DP (io), 6 P1_HS_DM (io), 7 P1_SS_TXB (io), 8 P1_SS_TXA (io), 9 P1_VDD12 (power), 10 P1_SS_RXB (io), 11 P1_SS_RXA (io), 12 UP_SS_TXB (io), 13 UP_SS_TXA (io), 14 UP_VDD12 (power), 15 UP_SS_RXB (io), 16 UP_SS_RXA (io), 17 UP_HS_DP (io), 18 UP_HS_DM (io), 19 P4_HS_DP (io), 20 P4_HS_DM (io), 21 P3_HS_DP (io), 22 P3_HS_DM (io), 23 P2_HS_DP (io), 24 P2_HS_DM (io), 25 P2_SS_RXA (io), 26 P2_SS_RXB (io), 27 P2_SS_TXA (io), 28 P2_SS_TXB (io), 29 VDD12 (power), 30 VDD33 (power), 31 RESET# (io), 32 OVCUR# (io)

## CH634M
designator U?
4 ports USB 3.0 SS hub
footprint QFN48_5X5
pins: 0 GND (power), 1 P2_HS_DP (io), 2 P2_HS_DM (io), 3 P2_SS_TXA (io), 4 P2_SS_TXB (io), 5 P2_SS_RXA (io), 6 P2_SS_RXB (io), 7 VDD12 (power), 8 VDD33 (power), 9 VDD5 (power), 10 VSW (power), 11 PWREN# (io), 12 HUB_CC/GPIO1 (io), 13 PWR_CC/GPIO0/BC_EN# (io), 14 OVCUR# (io), 15 SUSP/PDHUB# (io), 16 SMBCLK/SCL/EXCH# (io), 17 SMBDAT/SDA (io), 18 RESET# (io), 19 XO (io), 20 XI (in), 21 P1_HS_DP (io), 22 P1_HS_DM (io), 23 P1_SS_TXB (io), 24 P1_SS_TXA (io), 25 P1_VDD12 (power), 26 P1_SS_RXB (io), 27 P1_SS_RXA (io), 28 UP_HS_DP (io), 29 UP_HS_DM (io), 30 UP_SS_TXB (io), 31 UP_SS_TXA (io), 32 UP_VDD12 (power), 33 UP_SS_RXB (io), 34 UP_SS_RXA (io), 35 P4_SS_TXB (io), 36 P4_SS_TXA (io), 37 P4_VDD12 (power), 38 P4_SS_RXB (io), 39 P4_SS_RXA (io), 40 P4_HS_DP (io), 41 P4_HS_DM (io), 42 P3_SS_TXB (io), 43 P3_SS_TXA (io), 44 P3_VDD12 (power), 45 P3_SS_RXB (io), 46 P3_SS_RXA (io), 47 P3_HS_DP (io), 48 P3_HS_DM (io)

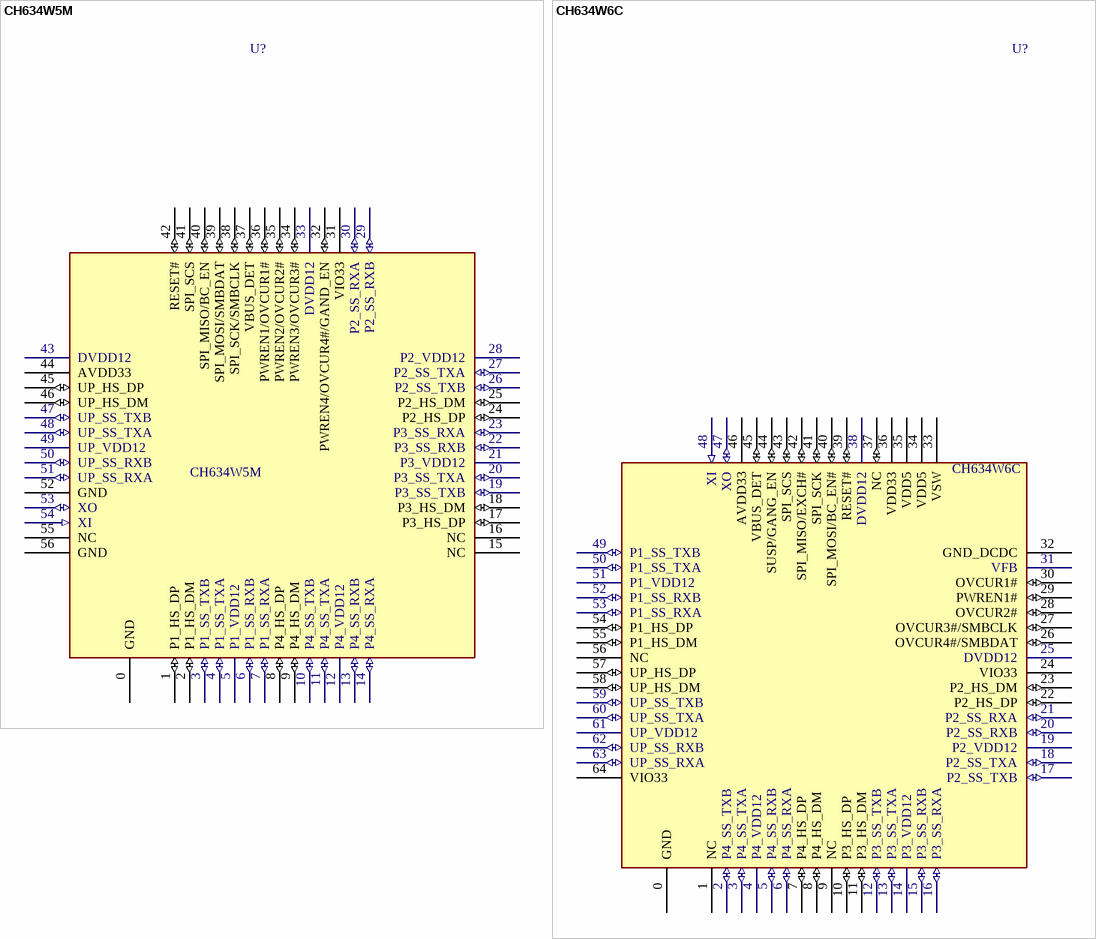
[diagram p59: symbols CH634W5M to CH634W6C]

## CH634W5M
designator U?
4 ports USB 3.0 SS hub
footprint QFN56_7x7
pins: 0 GND (power), 1 P1_HS_DP (io), 2 P1_HS_DM (io), 3 P1_SS_TXB (io), 4 P1_SS_TXA (io), 5 P1_VDD12 (power), 6 P1_SS_RXB (io), 7 P1_SS_RXA (io), 8 P4_HS_DP (io), 9 P4_HS_DM (io), 10 P4_SS_TXB (io), 11 P4_SS_TXA (io), 12 P4_VDD12 (power), 13 P4_SS_RXB (io), 14 P4_SS_RXA (io), 15 NC, 16 NC, 17 P3_HS_DP (io), 18 P3_HS_DM (io), 19 P3_SS_TXB (io), 20 P3_SS_TXA (io), 21 P3_VDD12 (power), 22 P3_SS_RXB (io), 23 P3_SS_RXA (io), 24 P2_HS_DP (io), 25 P2_HS_DM (io), 26 P2_SS_TXB (io), 27 P2_SS_TXA (io), 28 P2_VDD12 (power), 29 P2_SS_RXB (io), 30 P2_SS_RXA (io), 31 VIO33 (power), 32 PWREN4/OVCUR4#/GAND_EN (io), 33 DVDD12 (power), 34 PWREN3/OVCUR3# (io), 35 PWREN2/OVCUR2# (io), 36 PWREN1/OVCUR1# (io), 37 VBUS_DET (io), 38 SPI_SCK/SMBCLK (io), 39 SPI_MOSI/SMBDAT (io), 40 SPI_MISO/BC_EN (io), 41 SPI_SCS (io), 42 RESET# (io), 43 DVDD12 (power), 44 AVDD33 (power), 45 UP_HS_DP (io), 46 UP_HS_DM (io), 47 UP_SS_TXB (io), 48 UP_SS_TXA (io), 49 UP_VDD12 (power), 50 UP_SS_RXB (io), 51 UP_SS_RXA (io), 52 GND (power), 53 XO (io), 54 XI (in), 55 NC, 56 GND (power)

## CH634W6C
designator U?
4 ports USB 3.0 SS hub
footprint QFN64_8X8 (Footprint not found)
pins: 0 GND (power), 1 NC, 2 P4_SS_TXB (io), 3 P4_SS_TXA (io), 4 P4_VDD12 (power), 5 P4_SS_RXB (io), 6 P4_SS_RXA (io), 7 P4_HS_DP (io), 8 P4_HS_DM (io), 9 NC, 10 P3_HS_DP (io), 11 P3_HS_DM (io), 12 P3_SS_TXB (io), 13 P3_SS_TXA (io), 14 P3_VDD12 (power), 15 P3_SS_RXB (io), 16 P3_SS_RXA (io), 17 P2_SS_TXB (io), 18 P2_SS_TXA (io), 19 P2_VDD12 (power), 20 P2_SS_RXB (io), 21 P2_SS_RXA (io), 22 P2_HS_DP (io), 23 P2_HS_DM (io), 24 VIO33 (power), 25 DVDD12 (power), 26 OVCUR4#/SMBDAT (io), 27 OVCUR3#/SMBCLK (io), 28 OVCUR2# (io), 29 PWREN1# (io), 30 OVCUR1# (io), 31 VFB (power), 32 GND_DCDC (power), 33 VSW (power), 34 VDD5 (power), 35 VDD5 (power), 36 VDD33 (power), 37 NC (io), 38 DVDD12 (power), 39 RESET# (io), 40 SPI_MOSI/BC_EN# (io), 41 SPI_SCK (io), 42 SPI_MISO/EXCH# (io), 43 SPI_SCS (io), 44 SUSP/GANG_EN (io), 45 VBUS_DET (io), 46 AVDD33 (power), 47 XO (io), 48 XI (in), 49 P1_SS_TXB (io), 50 P1_SS_TXA (io), 51 P1_VDD12 (power), 52 P1_SS_RXB (io), 53 P1_SS_RXA (io), 54 P1_HS_DP (io), 55 P1_HS_DM (io), 56 NC, 57 UP_HS_DP (io), 58 UP_HS_DM (io), 59 UP_SS_TXB (io), 60 UP_SS_TXA (io), 61 UP_VDD12 (power), 62 UP_SS_RXB (io), 63 UP_SS_RXA (io), 64 VIO33 (power)

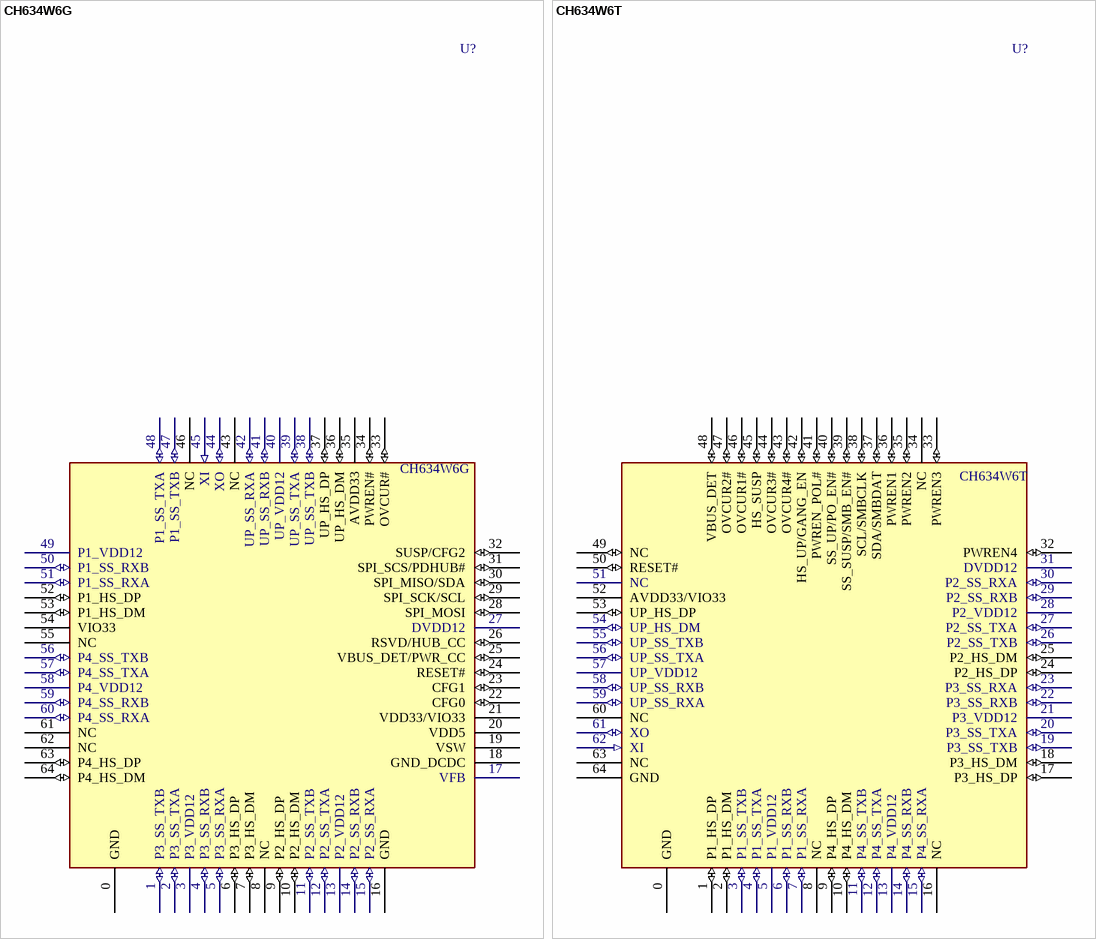
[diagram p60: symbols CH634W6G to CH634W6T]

## CH634W6G
designator U?
4 ports USB 3.0 SS hub
footprint QFN64_8X8 (Footprint not found)
pins: 0 GND (power), 1 P3_SS_TXB (io), 2 P3_SS_TXA (io), 3 P3_VDD12 (power), 4 P3_SS_RXB (io), 5 P3_SS_RXA (io), 6 P3_HS_DP (io), 7 P3_HS_DM (io), 8 NC, 9 P2_HS_DP (io), 10 P2_HS_DM (io), 11 P2_SS_TXB (io), 12 P2_SS_TXA (io), 13 P2_VDD12 (power), 14 P2_SS_RXB (io), 15 P2_SS_RXA (io), 16 GND (power), 17 VFB (power), 18 GND_DCDC (power), 19 VSW (power), 20 VDD5 (power), 21 VDD33/VIO33 (power), 22 CFG0 (io), 23 CFG1 (io), 24 RESET# (io), 25 VBUS_DET/PWR_CC (io), 26 RSVD/HUB_CC (io), 27 DVDD12 (power), 28 SPI_MOSI (io), 29 SPI_SCK/SCL (io), 30 SPI_MISO/SDA (io), 31 SPI_SCS/PDHUB# (io), 32 SUSP/CFG2 (io), 33 OVCUR# (io), 34 PWREN# (io), 35 AVDD33 (power), 36 UP_HS_DM (io), 37 UP_HS_DP (io), 38 UP_SS_TXB (io), 39 UP_SS_TXA (io), 40 UP_VDD12 (power), 41 UP_SS_RXB (io), 42 UP_SS_RXA (io), 43 NC, 44 XO (io), 45 XI (in), 46 NC, 47 P1_SS_TXB (io), 48 P1_SS_TXA (io), 49 P1_VDD12 (power), 50 P1_SS_RXB (io), 51 P1_SS_RXA (io), 52 P1_HS_DP (io), 53 P1_HS_DM (io), 54 VIO33 (power), 55 NC, 56 P4_SS_TXB (io), 57 P4_SS_TXA (io), 58 P4_VDD12 (power), 59 P4_SS_RXB (io), 60 P4_SS_RXA (io), 61 NC, 62 NC, 63 P4_HS_DP (io), 64 P4_HS_DM (io)

## CH634W6T
designator U?
4 ports USB 3.0 SS hub
footprint QFN64_9X9
pins: 0 GND (power), 1 P1_HS_DP (io), 2 P1_HS_DM (io), 3 P1_SS_TXB (io), 4 P1_SS_TXA (io), 5 P1_VDD12 (power), 6 P1_SS_RXB (io), 7 P1_SS_RXA (io), 8 NC, 9 P4_HS_DP (io), 10 P4_HS_DM (io), 11 P4_SS_TXB (io), 12 P4_SS_TXA (io), 13 P4_VDD12 (power), 14 P4_SS_RXB (io), 15 P4_SS_RXA (io), 16 NC, 17 P3_HS_DP (io), 18 P3_HS_DM (io), 19 P3_SS_TXB (io), 20 P3_SS_TXA (io), 21 P3_VDD12 (power), 22 P3_SS_RXB (io), 23 P3_SS_RXA (io), 24 P2_HS_DP (io), 25 P2_HS_DM (io), 26 P2_SS_TXB (io), 27 P2_SS_TXA (io), 28 P2_VDD12 (power), 29 P2_SS_RXB (io), 30 P2_SS_RXA (io), 31 DVDD12 (power), 32 PWREN4 (io), 33 PWREN3 (io), 34 NC, 35 PWREN2 (io), 36 PWREN1 (io), 37 SDA/SMBDAT (io), 38 SCL/SMBCLK (io), 39 SS_SUSP/SMB_EN# (io), 40 SS_UP/PO_EN# (io), 41 PWREN_POL# (io), 42 HS_UP/GANG_EN (io), 43 OVCUR4# (io), 44 OVCUR3# (io), 45 HS_SUSP (io), 46 OVCUR1# (io), 47 OVCUR2# (io), 48 VBUS_DET (io), 49 NC (io), 50 RESET# (io), 51 NC, 52 AVDD33/VIO33 (power), 53 UP_HS_DP (io), 54 UP_HS_DM (io), 55 UP_SS_TXB (io), 56 UP_SS_TXA (io), 57 UP_VDD12 (power), 58 UP_SS_RXB (io), 59 UP_SS_RXA (io), 60 NC, 61 XO (io), 62 XI (in), 63 NC, 64 GND (power)

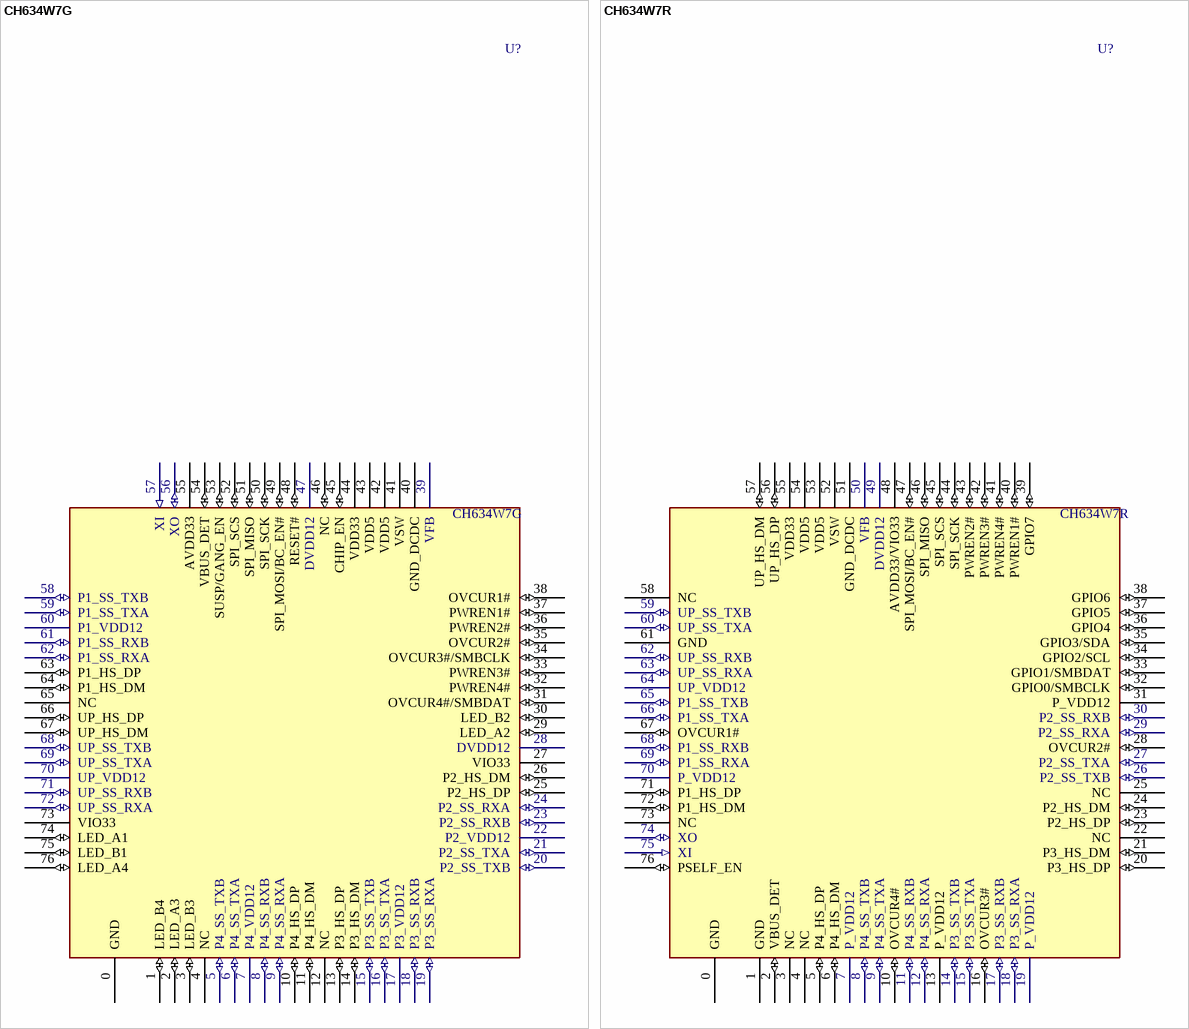
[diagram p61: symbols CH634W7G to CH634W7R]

## CH634W7G
designator U?
4 ports USB 3.0 SS hub
footprint QFN76_9X9
pins: 0 GND (power), 1 LED_B4 (io), 2 LED_A3 (io), 3 LED_B3 (io), 4 NC, 5 P4_SS_TXB (io), 6 P4_SS_TXA (io), 7 P4_VDD12 (power), 8 P4_SS_RXB (io), 9 P4_SS_RXA (io), 10 P4_HS_DP (io), 11 P4_HS_DM (io), 12 NC, 13 P3_HS_DP (io), 14 P3_HS_DM (io), 15 P3_SS_TXB (io), 16 P3_SS_TXA (io), 17 P3_VDD12 (power), 18 P3_SS_RXB (io), 19 P3_SS_RXA (io), 20 P2_SS_TXB (io), 21 P2_SS_TXA (io), 22 P2_VDD12 (power), 23 P2_SS_RXB (io), 24 P2_SS_RXA (io), 25 P2_HS_DP (io), 26 P2_HS_DM (io), 27 VIO33 (power), 28 DVDD12 (power), 29 LED_A2 (io), 30 LED_B2 (io), 31 OVCUR4#/SMBDAT (io), 32 PWREN4# (io), 33 PWREN3# (io), 34 OVCUR3#/SMBCLK (io), 35 OVCUR2# (io), 36 PWREN2# (io), 37 PWREN1# (io), 38 OVCUR1# (io), 39 VFB (power), 40 GND_DCDC (power), 41 VSW (power), 42 VDD5 (power), 43 VDD5 (power), 44 VDD33 (power), 45 CHIP_EN (io), 46 NC (io), 47 DVDD12 (power), 48 RESET# (io), 49 SPI_MOSI/BC_EN# (io), 50 SPI_SCK (io), 51 SPI_MISO (io), 52 SPI_SCS (io), 53 SUSP/GANG_EN (io), 54 VBUS_DET (io), 55 AVDD33 (power), 56 XO (io), 57 XI (in), 58 P1_SS_TXB (io), 59 P1_SS_TXA (io), 60 P1_VDD12 (power), 61 P1_SS_RXB (io), 62 P1_SS_RXA (io), 63 P1_HS_DP (io), 64 P1_HS_DM (io), 65 NC, 66 UP_HS_DP (io), 67 UP_HS_DM (io), 68 UP_SS_TXB (io), 69 UP_SS_TXA (io), 70 UP_VDD12 (power), 71 UP_SS_RXB (io), 72 UP_SS_RXA (io), 73 VIO33 (power), 74 LED_A1 (io), 75 LED_B1 (io), 76 LED_A4 (io)

## CH634W7R
designator U?
4 ports USB 3.0 SS hub
footprint QFN76_9X9
pins: 0 GND (power), 1 GND (power), 2 VBUS_DET (io), 3 NC, 4 NC, 5 P4_HS_DP (io), 6 P4_HS_DM (io), 7 P_VDD12 (power), 8 P4_SS_TXB (io), 9 P4_SS_TXA (io), 10 OVCUR4# (io), 11 P4_SS_RXB (io), 12 P4_SS_RXA (io), 13 P_VDD12 (power), 14 P3_SS_TXB (io), 15 P3_SS_TXA (io), 16 OVCUR3# (io), 17 P3_SS_RXB (io), 18 P3_SS_RXA (io), 19 P_VDD12 (power), 20 P3_HS_DP (io), 21 P3_HS_DM (io), 22 NC, 23 P2_HS_DP (io), 24 P2_HS_DM (io), 25 NC, 26 P2_SS_TXB (io), 27 P2_SS_TXA (io), 28 OVCUR2# (io), 29 P2_SS_RXA (io), 30 P2_SS_RXB (io), 31 P_VDD12 (power), 32 GPIO0/SMBCLK (io), 33 GPIO1/SMBDAT (io), 34 GPIO2/SCL (io), 35 GPIO3/SDA (io), 36 GPIO4 (io), 37 GPIO5 (io), 38 GPIO6 (io), 39 GPIO7 (io), 40 PWREN1# (io), 41 PWREN4# (io), 42 PWREN3# (io), 43 PWREN2# (io), 44 SPI_SCK (io), 45 SPI_SCS (io), 46 SPI_MISO (io), 47 SPI_MOSI/BC_EN# (io), 48 AVDD33/VIO33 (power), 49 DVDD12 (power), 50 VFB (power), 51 GND_DCDC (power), 52 VSW (power), 53 VDD5 (power), 54 VDD5 (power), 55 VDD33 (power), 56 UP_HS_DP (io), 57 UP_HS_DM (io), 58 NC, 59 UP_SS_TXB (io), 60 UP_SS_TXA (io), 61 GND (power), 62 UP_SS_RXB (io), 63 UP_SS_RXA (io), 64 UP_VDD12 (power), 65 P1_SS_TXB (io), 66 P1_SS_TXA (io), 67 OVCUR1# (io), 68 P1_SS_RXB (io), 69 P1_SS_RXA (io), 70 P_VDD12 (power), 71 P1_HS_DP (io), 72 P1_HS_DM (io), 73 NC, 74 XO (io), 75 XI (in), 76 PSELF_EN (io)

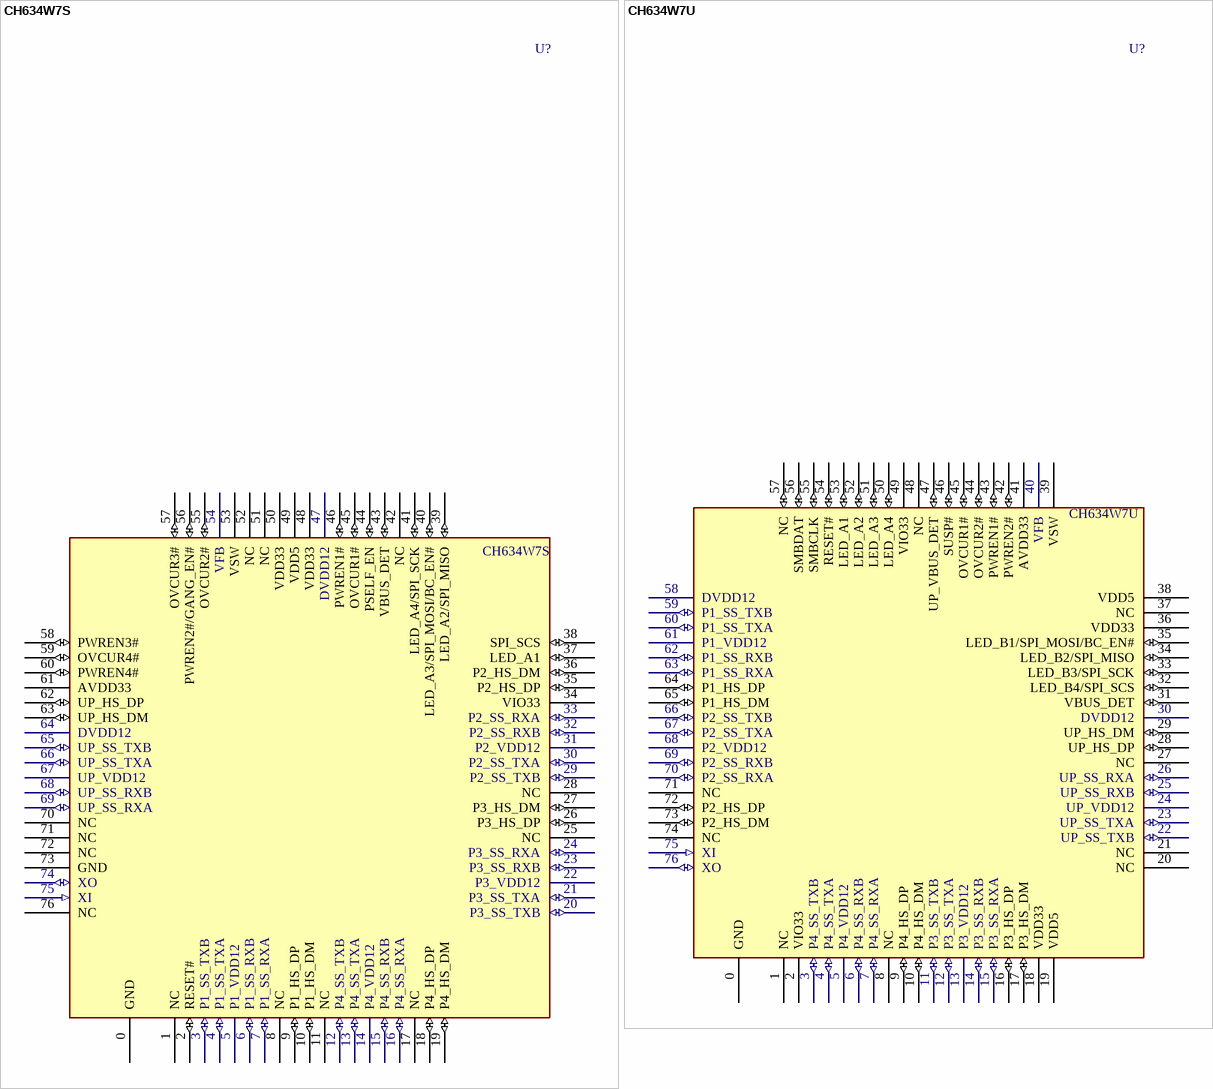
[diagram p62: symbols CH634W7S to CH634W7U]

## CH634W7S
designator U?
4 ports USB 3.0 SS hub
footprint QFN76_9X9
pins: 0 GND (power), 1 NC, 2 RESET# (io), 3 P1_SS_TXB (io), 4 P1_SS_TXA (io), 5 P1_VDD12 (power), 6 P1_SS_RXB (io), 7 P1_SS_RXA (io), 8 NC, 9 P1_HS_DP (io), 10 P1_HS_DM (io), 11 NC, 12 P4_SS_TXB (io), 13 P4_SS_TXA (io), 14 P4_VDD12 (power), 15 P4_SS_RXB (io), 16 P4_SS_RXA (io), 17 NC, 18 P4_HS_DP (io), 19 P4_HS_DM (io), 20 P3_SS_TXB (io), 21 P3_SS_TXA (io), 22 P3_VDD12 (power), 23 P3_SS_RXB (io), 24 P3_SS_RXA (io), 25 NC, 26 P3_HS_DP (io), 27 P3_HS_DM (io), 28 NC, 29 P2_SS_TXB (io), 30 P2_SS_TXA (io), 31 P2_VDD12 (power), 32 P2_SS_RXB (io), 33 P2_SS_RXA (io), 34 VIO33 (power), 35 P2_HS_DP (io), 36 P2_HS_DM (io), 37 LED_A1 (io), 38 SPI_SCS (io), 39 LED_A2/SPI_MISO (io), 40 LED_A3/SPI_MOSI/BC_EN# (io), 41 LED_A4/SPI_SCK (io), 42 NC, 43 VBUS_DET (io), 44 PSELF_EN (io), 45 OVCUR1# (io), 46 PWREN1# (io), 47 DVDD12 (power), 48 VDD33 (power), 49 VDD5 (power), 50 VDD33 (power), 51 NC, 52 NC, 53 VSW (power), 54 VFB (power), 55 OVCUR2# (io), 56 PWREN2#/GANG_EN# (io), 57 OVCUR3# (io), 58 PWREN3# (io), 59 OVCUR4# (io), 60 PWREN4# (io), 61 AVDD33 (power), 62 UP_HS_DP (io), 63 UP_HS_DM (io), 64 DVDD12 (power), 65 UP_SS_TXB (io), 66 UP_SS_TXA (io), 67 UP_VDD12 (power), 68 UP_SS_RXB (io), 69 UP_SS_RXA (io), 70 NC, 71 NC, 72 NC, 73 GND (power), 74 XO (io), 75 XI (in), 76 NC

## CH634W7U
designator U?
4 ports USB 3.0 SS hub
footprint QFN76_9X9
pins: 0 GND (power), 1 NC, 2 VIO33 (power), 3 P4_SS_TXB (io), 4 P4_SS_TXA (io), 5 P4_VDD12 (power), 6 P4_SS_RXB (io), 7 P4_SS_RXA (io), 8 NC, 9 P4_HS_DP (io), 10 P4_HS_DM (io), 11 P3_SS_TXB (io), 12 P3_SS_TXA (io), 13 P3_VDD12 (power), 14 P3_SS_RXB (io), 15 P3_SS_RXA (io), 16 P3_HS_DP (io), 17 P3_HS_DM (io), 18 VDD33 (power), 19 VDD5 (power), 20 NC, 21 NC, 22 UP_SS_TXB (io), 23 UP_SS_TXA (io), 24 UP_VDD12 (power), 25 UP_SS_RXB (io), 26 UP_SS_RXA (io), 27 NC, 28 UP_HS_DP (io), 29 UP_HS_DM (io), 30 DVDD12 (power), 31 VBUS_DET (io), 32 LED_B4/SPI_SCS (io), 33 LED_B3/SPI_SCK (io), 34 LED_B2/SPI_MISO (io), 35 LED_B1/SPI_MOSI/BC_EN# (io), 36 VDD33 (power), 37 NC, 38 VDD5 (power), 39 VSW (power), 40 VFB (power), 41 AVDD33 (power), 42 PWREN2# (io), 43 PWREN1# (io), 44 OVCUR2# (io), 45 OVCUR1# (io), 46 SUSP# (io), 47 UP_VBUS_DET (io), 48 NC, 49 VIO33 (power), 50 LED_A4 (io), 51 LED_A3 (io), 52 LED_A2 (io), 53 LED_A1 (io), 54 RESET# (io), 55 SMBCLK (io), 56 SMBDAT (io), 57 NC (io), 58 DVDD12 (power), 59 P1_SS_TXB (io), 60 P1_SS_TXA (io), 61 P1_VDD12 (power), 62 P1_SS_RXB (io), 63 P1_SS_RXA (io), 64 P1_HS_DP (io), 65 P1_HS_DM (io), 66 P2_SS_TXB (io), 67 P2_SS_TXA (io), 68 P2_VDD12 (power), 69 P2_SS_RXB (io), 70 P2_SS_RXA (io), 71 NC, 72 P2_HS_DP (io), 73 P2_HS_DM (io), 74 NC, 75 XI (in), 76 XO (io)

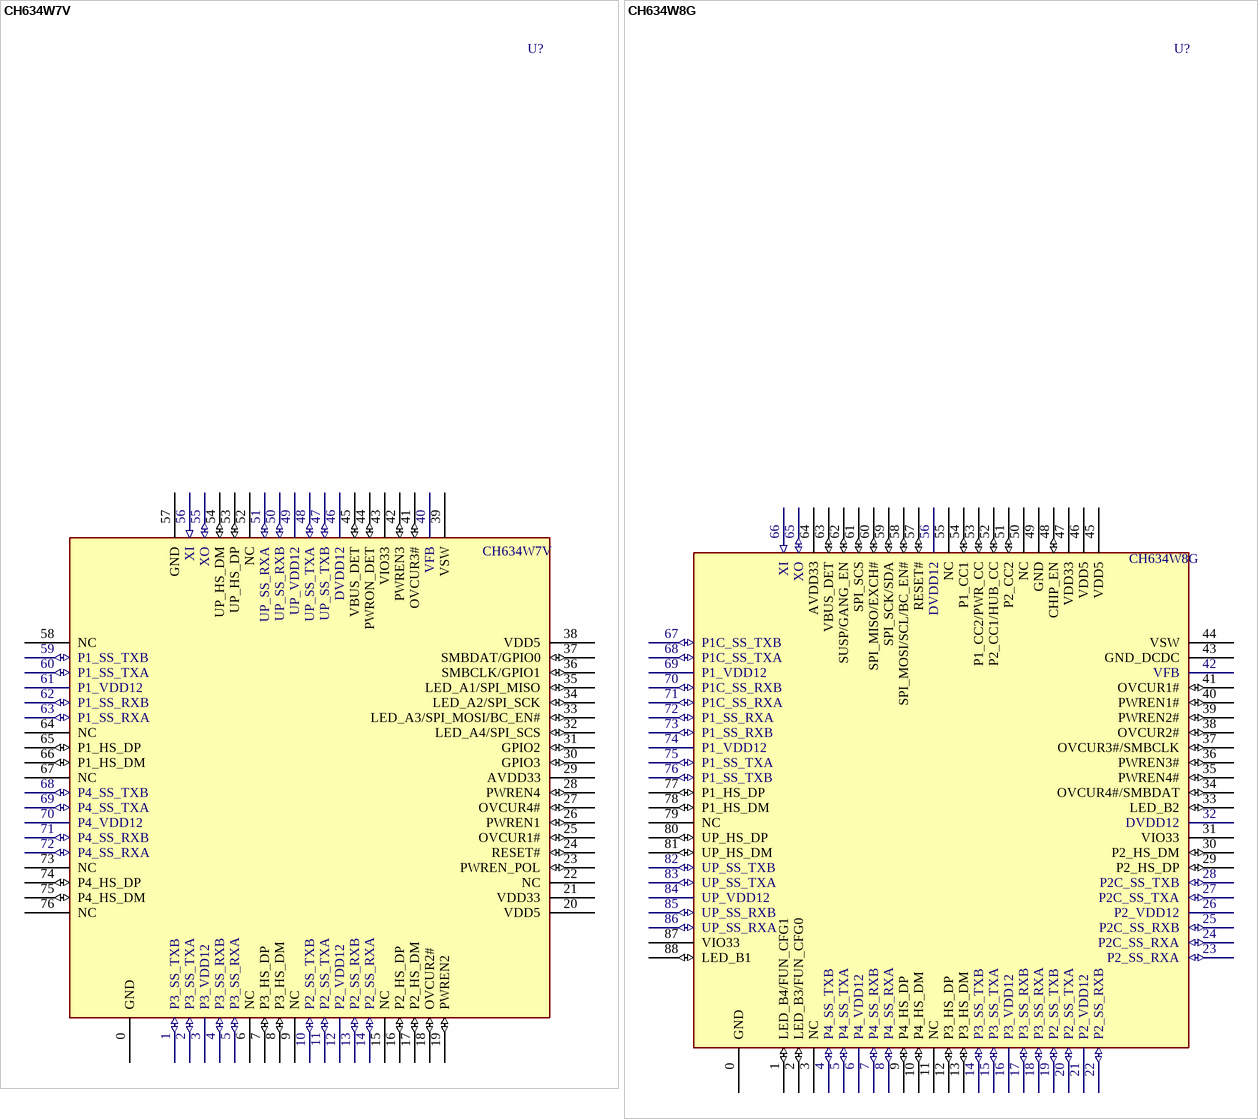
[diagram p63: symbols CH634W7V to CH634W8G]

## CH634W7V
designator U?
4 ports USB 3.0 SS hub
footprint QFN76_9X9
pins: 0 GND (power), 1 P3_SS_TXB (io), 2 P3_SS_TXA (io), 3 P3_VDD12 (power), 4 P3_SS_RXB (io), 5 P3_SS_RXA (io), 6 NC, 7 P3_HS_DP (io), 8 P3_HS_DM (io), 9 NC, 10 P2_SS_TXB (io), 11 P2_SS_TXA (io), 12 P2_VDD12 (power), 13 P2_SS_RXB (io), 14 P2_SS_RXA (io), 15 NC, 16 P2_HS_DP (io), 17 P2_HS_DM (io), 18 OVCUR2# (io), 19 PWREN2 (io), 20 VDD5 (power), 21 VDD33 (power), 22 NC, 23 PWREN_POL (io), 24 RESET# (io), 25 OVCUR1# (io), 26 PWREN1 (io), 27 OVCUR4# (io), 28 PWREN4 (io), 29 AVDD33 (power), 30 GPIO3 (io), 31 GPIO2 (io), 32 LED_A4/SPI_SCS (io), 33 LED_A3/SPI_MOSI/BC_EN# (io), 34 LED_A2/SPI_SCK (io), 35 LED_A1/SPI_MISO (io), 36 SMBCLK/GPIO1 (io), 37 SMBDAT/GPIO0 (io), 38 VDD5 (power), 39 VSW (power), 40 VFB (power), 41 OVCUR3# (io), 42 PWREN3 (io), 43 VIO33 (power), 44 PWRON_DET (io), 45 VBUS_DET (io), 46 DVDD12 (power), 47 UP_SS_TXB (io), 48 UP_SS_TXA (io), 49 UP_VDD12 (power), 50 UP_SS_RXB (io), 51 UP_SS_RXA (io), 52 NC, 53 UP_HS_DP (io), 54 UP_HS_DM (io), 55 XO (io), 56 XI (in), 57 GND (power), 58 NC, 59 P1_SS_TXB (io), 60 P1_SS_TXA (io), 61 P1_VDD12 (power), 62 P1_SS_RXB (io), 63 P1_SS_RXA (io), 64 NC, 65 P1_HS_DP (io), 66 P1_HS_DM (io), 67 NC, 68 P4_SS_TXB (io), 69 P4_SS_TXA (io), 70 P4_VDD12 (power), 71 P4_SS_RXB (io), 72 P4_SS_RXA (io), 73 NC, 74 P4_HS_DP (io), 75 P4_HS_DM (io), 76 NC

## CH634W8G
designator U?
4 ports USB 3.0 SS hub
footprint QFN88_10X10
pins: 0 GND (power), 1 LED_B4/FUN_CFG1 (io), 2 LED_B3/FUN_CFG0 (io), 3 NC, 4 P4_SS_TXB (io), 5 P4_SS_TXA (io), 6 P4_VDD12 (power), 7 P4_SS_RXB (io), 8 P4_SS_RXA (io), 9 P4_HS_DP (io), 10 P4_HS_DM (io), 11 NC, 12 P3_HS_DP (io), 13 P3_HS_DM (io), 14 P3_SS_TXB (io), 15 P3_SS_TXA (io), 16 P3_VDD12 (power), 17 P3_SS_RXB (io), 18 P3_SS_RXA (io), 19 P2_SS_TXB (io), 20 P2_SS_TXA (io), 21 P2_VDD12 (power), 22 P2_SS_RXB (io), 23 P2_SS_RXA (io), 24 P2C_SS_RXA (io), 25 P2C_SS_RXB (io), 26 P2_VDD12 (power), 27 P2C_SS_TXA (io), 28 P2C_SS_TXB (io), 29 P2_HS_DP (io), 30 P2_HS_DM (io), 31 VIO33 (power), 32 DVDD12 (power), 33 LED_B2 (io), 34 OVCUR4#/SMBDAT (io), 35 PWREN4# (io), 36 PWREN3# (io), 37 OVCUR3#/SMBCLK (io), 38 OVCUR2# (io), 39 PWREN2# (io), 40 PWREN1# (io), 41 OVCUR1# (io), 42 VFB (power), 43 GND_DCDC (power), 44 VSW (power), 45 VDD5 (power), 46 VDD5 (power), 47 VDD33 (power), 48 CHIP_EN (io), 49 GND (power), 50 NC, 51 P2_CC2 (io), 52 P2_CC1/HUB_CC (io), 53 P1_CC2/PWR_CC (io), 54 P1_CC1 (io), 55 NC, 56 DVDD12 (power), 57 RESET# (io), 58 SPI_MOSI/SCL/BC_EN# (io), 59 SPI_SCK/SDA (io), 60 SPI_MISO/EXCH# (io), 61 SPI_SCS (io), 62 SUSP/GANG_EN (io), 63 VBUS_DET (io), 64 AVDD33 (power), 65 XO (io), 66 XI (in), 67 P1C_SS_TXB (io), 68 P1C_SS_TXA (io), 69 P1_VDD12 (power), 70 P1C_SS_RXB (io), 71 P1C_SS_RXA (io), 72 P1_SS_RXA (io), 73 P1_SS_RXB (io), 74 P1_VDD12 (power), 75 P1_SS_TXA (io), 76 P1_SS_TXB (io), 77 P1_HS_DP (io), 78 P1_HS_DM (io), 79 NC, 80 UP_HS_DP (io), 81 UP_HS_DM (io), 82 UP_SS_TXB (io), 83 UP_SS_TXA (io), 84 UP_VDD12 (power), 85 UP_SS_RXB (io), 86 UP_SS_RXA (io), 87 VIO33 (power), 88 LED_B1 (io)

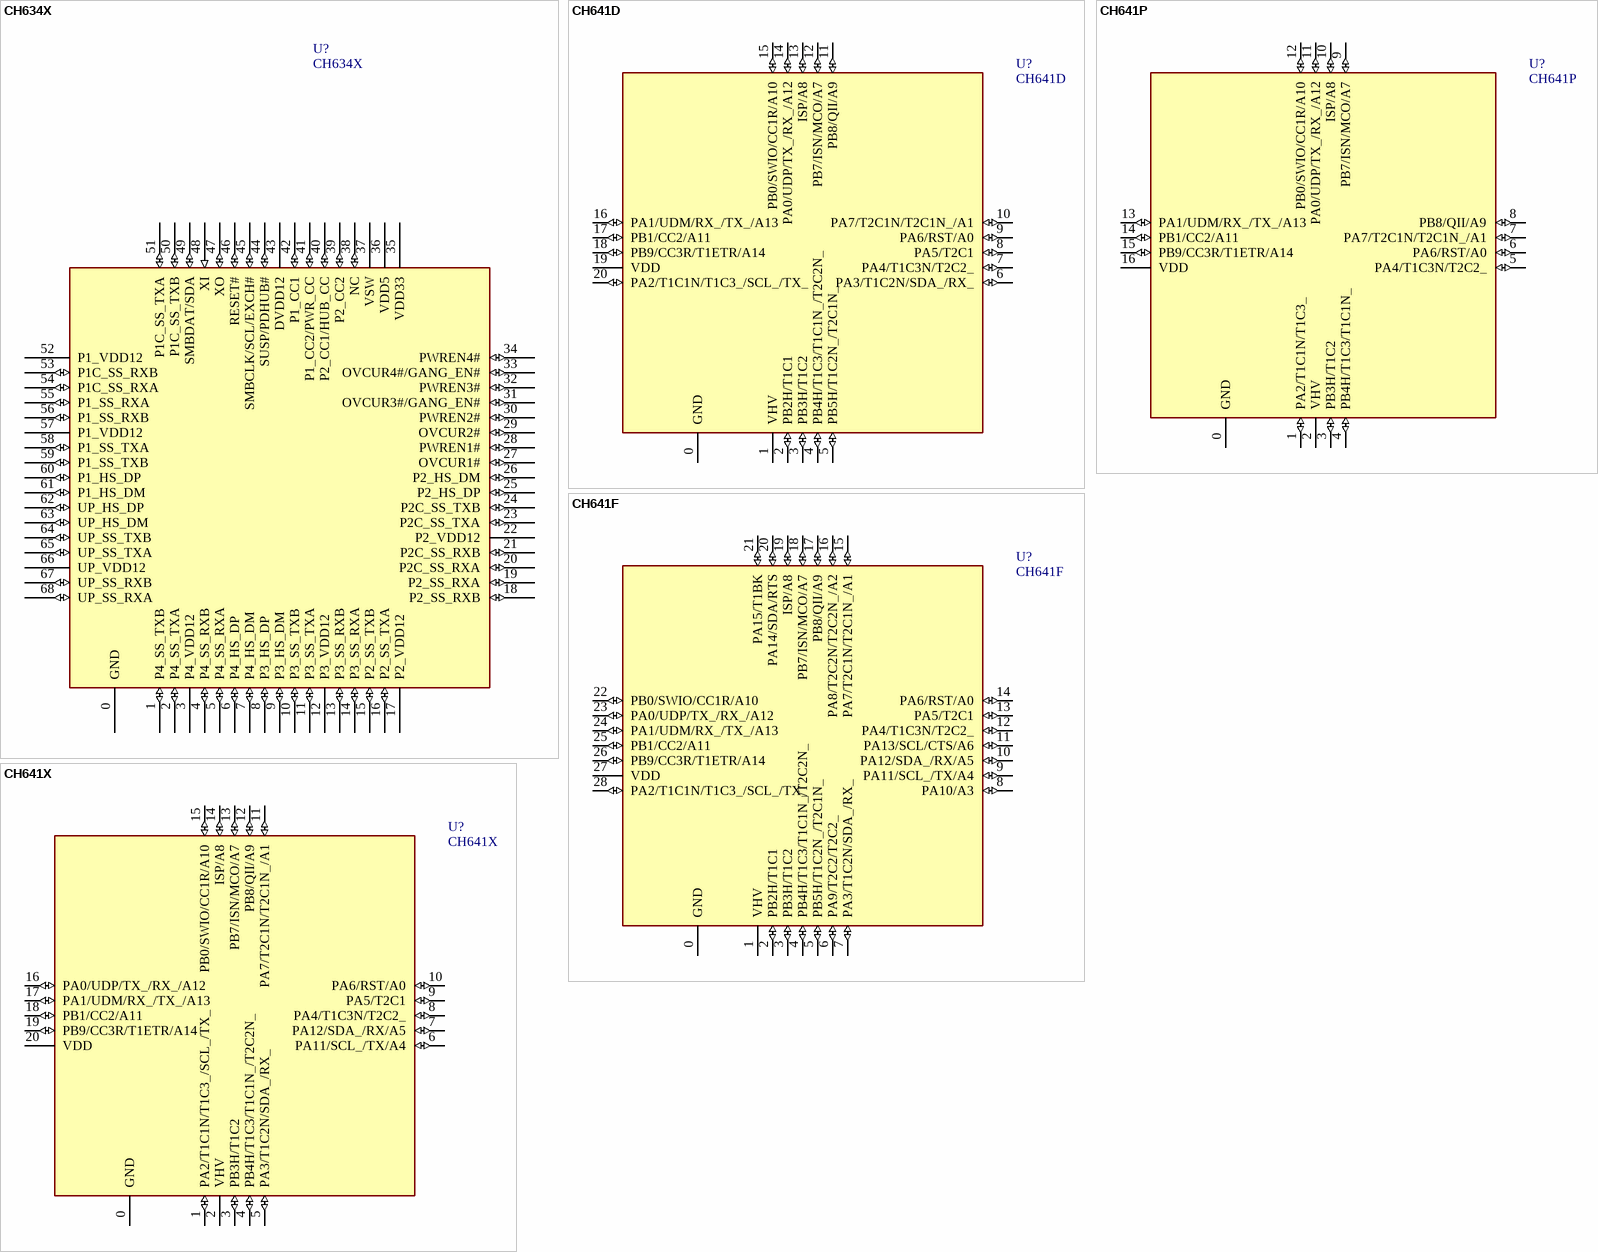
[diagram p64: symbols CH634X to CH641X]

## CH634X
designator U?
4 ports USB 3.0 SS hub
footprint QFN68_8X8
pins: 0 GND (power), 1 P4_SS_TXB (io), 2 P4_SS_TXA (io), 3 P4_VDD12 (power), 4 P4_SS_RXB (io), 5 P4_SS_RXA (io), 6 P4_HS_DP (io), 7 P4_HS_DM (io), 8 P3_HS_DP (io), 9 P3_HS_DM (io), 10 P3_SS_TXB (io), 11 P3_SS_TXA (io), 12 P3_VDD12 (power), 13 P3_SS_RXB (io), 14 P3_SS_RXA (io), 15 P2_SS_TXB (io), 16 P2_SS_TXA (io), 17 P2_VDD12 (power), 18 P2_SS_RXB (io), 19 P2_SS_RXA (io), 20 P2C_SS_RXA (io), 21 P2C_SS_RXB (io), 22 P2_VDD12 (power), 23 P2C_SS_TXA (io), 24 P2C_SS_TXB (io), 25 P2_HS_DP (io), 26 P2_HS_DM (io), 27 OVCUR1# (io), 28 PWREN1# (io), 29 OVCUR2# (io), 30 PWREN2# (io), 31 OVCUR3#/GANG_EN# (io), 32 PWREN3# (io), 33 OVCUR4#/GANG_EN# (io), 34 PWREN4# (io), 35 VDD33 (power), 36 VDD5 (power), 37 VSW (power), 38 NC (io), 39 P2_CC2 (io), 40 P2_CC1/HUB_CC (io), 41 P1_CC2/PWR_CC (io), 42 P1_CC1 (io), 43 DVDD12 (power), 44 SUSP/PDHUB# (io), 45 SMBCLK/SCL/EXCH# (io), 46 RESET# (io), 47 XO (io), 48 XI (in), 49 SMBDAT/SDA (io), 50 P1C_SS_TXB (io), 51 P1C_SS_TXA (io), 52 P1_VDD12 (power), 53 P1C_SS_RXB (io), 54 P1C_SS_RXA (io), 55 P1_SS_RXA (io), 56 P1_SS_RXB (io), 57 P1_VDD12 (power), 58 P1_SS_TXA (io), 59 P1_SS_TXB (io), 60 P1_HS_DP (io), 61 P1_HS_DM (io), 62 UP_HS_DP (io), 63 UP_HS_DM (io), 64 UP_SS_TXB (io), 65 UP_SS_TXA (io), 66 UP_VDD12 (power), 67 UP_SS_RXB (io), 68 UP_SS_RXA (io)

## CH641D
designator U?
RISC-V MCU with PD/ADC/UART/OA, for wireless charging
footprint QFN20_3X3
pins: 0 GND (power), 1 VHV (power), 2 PB2H/T1C1 (io), 3 PB3H/T1C2 (io), 4 PB4H/T1C3/T1C1N_/T2C2N_ (io), 5 PB5H/T1C2N_/T2C1N_ (io), 6 PA3/T1C2N/SDA_/RX_ (io), 7 PA4/T1C3N/T2C2_ (io), 8 PA5/T2C1 (io), 9 PA6/RST/A0 (io), 10 PA7/T2C1N/T2C1N_/A1 (io), 11 PB8/QII/A9 (io), 12 PB7/ISN/MCO/A7 (io), 13 ISP/A8 (io), 14 PA0/UDP/TX_/RX_/A12 (io), 15 PB0/SWIO/CC1R/A10 (io), 16 PA1/UDM/RX_/TX_/A13 (io), 17 PB1/CC2/A11 (io), 18 PB9/CC3R/T1ETR/A14 (io), 19 VDD (power), 20 PA2/T1C1N/T1C3_/SCL_/TX_ (io)

## CH641F
designator U?
RISC-V MCU with PD/ADC/UART/OA, for wireless charging
footprint QFN28_4X4
pins: 0 GND (power), 1 VHV (power), 2 PB2H/T1C1 (io), 3 PB3H/T1C2 (io), 4 PB4H/T1C3/T1C1N_/T2C2N_ (io), 5 PB5H/T1C2N_/T2C1N_ (io), 6 PA9/T2C2/T2C2_ (io), 7 PA3/T1C2N/SDA_/RX_ (io), 8 PA10/A3 (io), 9 PA11/SCL_/TX/A4 (io), 10 PA12/SDA_/RX/A5 (io), 11 PA13/SCL/CTS/A6 (io), 12 PA4/T1C3N/T2C2_ (io), 13 PA5/T2C1 (io), 14 PA6/RST/A0 (io), 15 PA7/T2C1N/T2C1N_/A1 (io), 16 PA8/T2C2N/T2C2N_/A2 (io), 17 PB8/QII/A9 (io), 18 PB7/ISN/MCO/A7 (io), 19 ISP/A8 (io), 20 PA14/SDA/RTS (io), 21 PA15/T1BK (io), 22 PB0/SWIO/CC1R/A10 (io), 23 PA0/UDP/TX_/RX_/A12 (io), 24 PA1/UDM/RX_/TX_/A13 (io), 25 PB1/CC2/A11 (io), 26 PB9/CC3R/T1ETR/A14 (io), 27 VDD (power), 28 PA2/T1C1N/T1C3_/SCL_/TX_ (io)

## CH641P
designator U?
RISC-V MCU with PD/ADC/UART/OA, for wireless charging
footprint QFN16_3X3
pins: 0 GND (power), 1 PA2/T1C1N/T1C3_ (io), 2 VHV (power), 3 PB3H/T1C2 (io), 4 PB4H/T1C3/T1C1N_ (io), 5 PA4/T1C3N/T2C2_ (io), 6 PA6/RST/A0 (io), 7 PA7/T2C1N/T2C1N_/A1 (io), 8 PB8/QII/A9 (io), 9 PB7/ISN/MCO/A7 (io), 10 ISP/A8 (io), 11 PA0/UDP/TX_/RX_/A12 (io), 12 PB0/SWIO/CC1R/A10 (io), 13 PA1/UDM/RX_/TX_/A13 (io), 14 PB1/CC2/A11 (io), 15 PB9/CC3R/T1ETR/A14 (io), 16 VDD (power)

## CH641X
designator U?
RISC-V MCU with PD/ADC/UART/OA, for wireless charging
footprint QFN20_3X3
pins: 0 GND (power), 1 PA2/T1C1N/T1C3_/SCL_/TX_ (io), 2 VHV (power), 3 PB3H/T1C2 (io), 4 PB4H/T1C3/T1C1N_/T2C2N_ (io), 5 PA3/T1C2N/SDA_/RX_ (io), 6 PA11/SCL_/TX/A4 (io), 7 PA12/SDA_/RX/A5 (io), 8 PA4/T1C3N/T2C2_ (io), 9 PA5/T2C1 (io), 10 PA6/RST/A0 (io), 11 PA7/T2C1N/T2C1N_/A1 (io), 12 PB8/QII/A9 (io), 13 PB7/ISN/MCO/A7 (io), 14 ISP/A8 (io), 15 PB0/SWIO/CC1R/A10 (io), 16 PA0/UDP/TX_/RX_/A12 (io), 17 PA1/UDM/RX_/TX_/A13 (io), 18 PB1/CC2/A11 (io), 19 PB9/CC3R/T1ETR/A14 (io), 20 VDD (power)

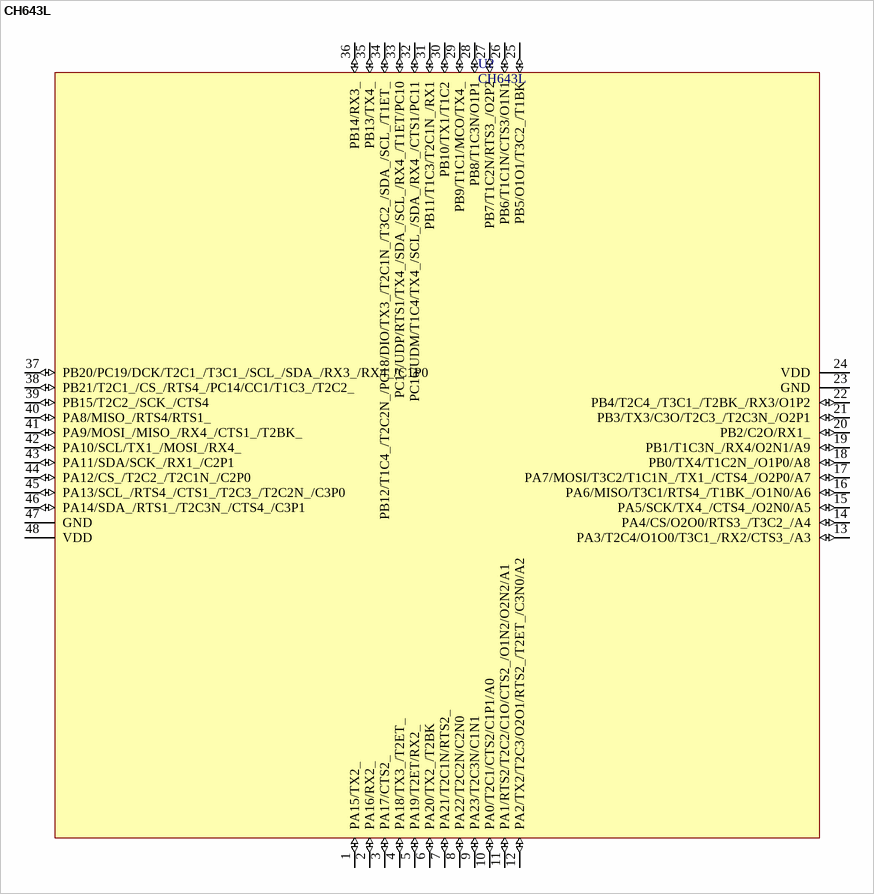
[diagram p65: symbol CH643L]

## CH643L
designator U?
RISC-V MCU with USB/RGB/ADC/SPI/I2C/4*UART/PD
footprint LQFP48 (Footprint not found)
pins: 1 PA15/TX2_ (io), 2 PA16/RX2_ (io), 3 PA17/CTS2_ (io), 4 PA18/TX3_/T2ET_ (io), 5 PA19/T2ET/RX2_ (io), 6 PA20/TX2_/T2BK (io), 7 PA21/T2C1N/RTS2_ (io), 8 PA22/T2C2N/C2N0 (io), 9 PA23/T2C3N/C1N1 (io), 10 PA0/T2C1/CTS2/C1P1/A0 (io), 11 PA1/RTS2/T2C2/C1O/CTS2_/O1N2/O2N2/A1 (io), 12 PA2/TX2/T2C3/O2O1/RTS2_/T2ET_/C3N0/A2 (io), 13 PA3/T2C4/O1O0/T3C1_/RX2/CTS3_/A3 (io), 14 PA4/CS/O2O0/RTS3_/T3C2_/A4 (io), 15 PA5/SCK/TX4_/CTS4_/O2N0/A5 (io), 16 PA6/MISO/T3C1/RTS4_/T1BK_/O1N0/A6 (io), 17 PA7/MOSI/T3C2/T1C1N_/TX1_/CTS4_/O2P0/A7 (io), 18 PB0/TX4/T1C2N_/O1P0/A8 (io), 19 PB1/T1C3N_/RX4/O2N1/A9 (io), 20 PB2/C2O/RX1_ (io), 21 PB3/TX3/C3O/T2C3_/T2C3N_/O2P1 (io), 22 PB4/T2C4_/T3C1_/T2BK_/RX3/O1P2 (io), 23 GND (power), 24 VDD (power), 25 PB5/O1O1/T3C2_/T1BK (io), 26 PB6/T1C1N/CTS3/O1N1 (io), 27 PB7/T1C2N/RTS3_/O2P2 (io), 28 PB8/T1C3N/O1P1 (io), 29 PB9/T1C1/MCO/TX4_ (io), 30 PB10/TX1/T1C2 (io), 31 PB11/T1C3/T2C1N_/RX1 (io), 32 PC16/UDM/T1C4/TX4_/SCL_/SDA_/RX4_/CTS1/PC11 (io), 33 PC17/UDP/RTS1/TX4_/SDA_/SCL_/RX4_/T1ET/PC10 (io), 34 PB12/T1C4_/T2C2N_/PC18/DIO/TX3_/T2C1N_/T3C2_/SDA_/SCL_/T1ET_ (io), 35 PB13/TX4_ (io), 36 PB14/RX3_ (io), 37 PB20/PC19/DCK/T2C1_/T3C1_/SCL_/SDA_/RX3_/RX4_/C1P0 (io), 38 PB21/T2C1_/CS_/RTS4_/PC14/CC1/T1C3_/T2C2_ (io), 39 PB15/T2C2_/SCK_/CTS4 (io), 40 PA8/MISO_/RTS4/RTS1_ (io), 41 PA9/MOSI_/MISO_/RX4_/CTS1_/T2BK_ (io), 42 PA10/SCL/TX1_/MOSI_/RX4_ (io), 43 PA11/SDA/SCK_/RX1_/C2P1 (io), 44 PA12/CS_/T2C2_/T2C1N_/C2P0 (io), 45 PA13/SCL_/RTS4_/CTS1_/T2C3_/T2C2N_/C3P0 (io), 46 PA14/SDA_/RTS1_/T2C3N_/CTS4_/C3P1 (io), 47 GND (power), 48 VDD (power)

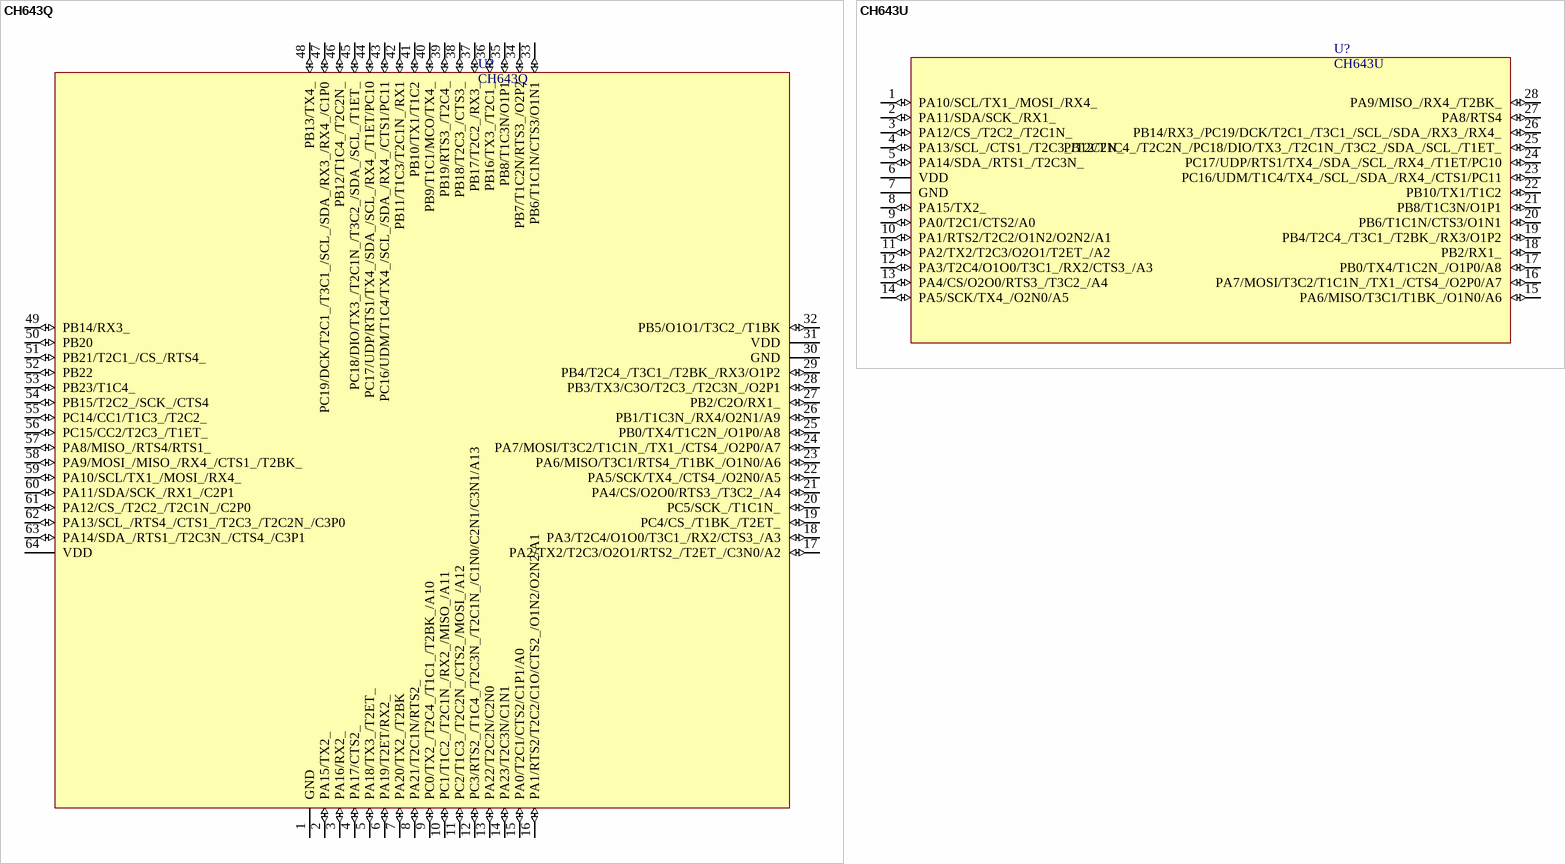
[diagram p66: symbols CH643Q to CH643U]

## CH643Q
designator U?
RISC-V MCU with USB/RGB/ADC/SPI/I2C/4*UART/PD
footprint LQFP64 (Footprint not found)
pins: 1 GND (power), 2 PA15/TX2_ (io), 3 PA16/RX2_ (io), 4 PA17/CTS2_ (io), 5 PA18/TX3_/T2ET_ (io), 6 PA19/T2ET/RX2_ (io), 7 PA20/TX2_/T2BK (io), 8 PA21/T2C1N/RTS2_ (io), 9 PC0/TX2_/T2C4_/T1C1_/T2BK_/A10 (io), 10 PC1/T1C2_/T2C1N_/RX2_/MISO_/A11 (io), 11 PC2/T1C3_/T2C2N_/CTS2_/MOSI_/A12 (io), 12 PC3/RTS2_/T1C4_/T2C3N_/T2C1N_/C1N0/C2N1/C3N1/A13 (io), 13 PA22/T2C2N/C2N0 (io), 14 PA23/T2C3N/C1N1 (io), 15 PA0/T2C1/CTS2/C1P1/A0 (io), 16 PA1/RTS2/T2C2/C1O/CTS2_/O1N2/O2N2/A1 (io), 17 PA2/TX2/T2C3/O2O1/RTS2_/T2ET_/C3N0/A2 (io), 18 PA3/T2C4/O1O0/T3C1_/RX2/CTS3_/A3 (io), 19 PC4/CS_/T1BK_/T2ET_ (io), 20 PC5/SCK_/T1C1N_ (io), 21 PA4/CS/O2O0/RTS3_/T3C2_/A4 (io), 22 PA5/SCK/TX4_/CTS4_/O2N0/A5 (io), 23 PA6/MISO/T3C1/RTS4_/T1BK_/O1N0/A6 (io), 24 PA7/MOSI/T3C2/T1C1N_/TX1_/CTS4_/O2P0/A7 (io), 25 PB0/TX4/T1C2N_/O1P0/A8 (io), 26 PB1/T1C3N_/RX4/O2N1/A9 (io), 27 PB2/C2O/RX1_ (io), 28 PB3/TX3/C3O/T2C3_/T2C3N_/O2P1 (io), 29 PB4/T2C4_/T3C1_/T2BK_/RX3/O1P2 (io), 30 GND (power), 31 VDD (power), 32 PB5/O1O1/T3C2_/T1BK (io), 33 PB6/T1C1N/CTS3/O1N1 (io), 34 PB7/T1C2N/RTS3_/O2P2 (io), 35 PB8/T1C3N/O1P1 (io), 36 PB16/TX3_/T2C1_ (io), 37 PB17/T2C2_/RX3_ (io), 38 PB18/T2C3_/CTS3_ (io), 39 PB19/RTS3_/T2C4_ (io), 40 PB9/T1C1/MCO/TX4_ (io), 41 PB10/TX1/T1C2 (io), 42 PB11/T1C3/T2C1N_/RX1 (io), 43 PC16/UDM/T1C4/TX4_/SCL_/SDA_/RX4_/CTS1/PC11 (io), 44 PC17/UDP/RTS1/TX4_/SDA_/SCL_/RX4_/T1ET/PC10 (io), 45 PC18/DIO/TX3_/T2C1N_/T3C2_/SDA_/SCL_/T1ET_ (io), 46 PB12/T1C4_/T2C2N_ (io), 47 PC19/DCK/T2C1_/T3C1_/SCL_/SDA_/RX3_/RX4_/C1P0 (io), 48 PB13/TX4_ (io), 49 PB14/RX3_ (io), 50 PB20 (io), 51 PB21/T2C1_/CS_/RTS4_ (io), 52 PB22 (io), 53 PB23/T1C4_ (io), 54 PB15/T2C2_/SCK_/CTS4 (io), 55 PC14/CC1/T1C3_/T2C2_ (io), 56 PC15/CC2/T2C3_/T1ET_ (io), 57 PA8/MISO_/RTS4/RTS1_ (io), 58 PA9/MOSI_/MISO_/RX4_/CTS1_/T2BK_ (io), 59 PA10/SCL/TX1_/MOSI_/RX4_ (io), 60 PA11/SDA/SCK_/RX1_/C2P1 (io), 61 PA12/CS_/T2C2_/T2C1N_/C2P0 (io), 62 PA13/SCL_/RTS4_/CTS1_/T2C3_/T2C2N_/C3P0 (io), 63 PA14/SDA_/RTS1_/T2C3N_/CTS4_/C3P1 (io), 64 VDD (power)

## CH643U
designator U?
RISC-V MCU with USB/RGB/ADC/SPI/I2C/4*UART
footprint QSOP28 (Footprint not found)
pins: 1 PA10/SCL/TX1_/MOSI_/RX4_ (io), 2 PA11/SDA/SCK_/RX1_ (io), 3 PA12/CS_/T2C2_/T2C1N_ (io), 4 PA13/SCL_/CTS1_/T2C3_/T2C2N_ (io), 5 PA14/SDA_/RTS1_/T2C3N_ (io), 6 VDD (power), 7 GND (power), 8 PA15/TX2_ (io), 9 PA0/T2C1/CTS2/A0 (io), 10 PA1/RTS2/T2C2/O1N2/O2N2/A1 (io), 11 PA2/TX2/T2C3/O2O1/T2ET_/A2 (io), 12 PA3/T2C4/O1O0/T3C1_/RX2/CTS3_/A3 (io), 13 PA4/CS/O2O0/RTS3_/T3C2_/A4 (io), 14 PA5/SCK/TX4_/O2N0/A5 (io), 15 PA6/MISO/T3C1/T1BK_/O1N0/A6 (io), 16 PA7/MOSI/T3C2/T1C1N_/TX1_/CTS4_/O2P0/A7 (io), 17 PB0/TX4/T1C2N_/O1P0/A8 (io), 18 PB2/RX1_ (io), 19 PB4/T2C4_/T3C1_/T2BK_/RX3/O1P2 (io), 20 PB6/T1C1N/CTS3/O1N1 (io), 21 PB8/T1C3N/O1P1 (io), 22 PB10/TX1/T1C2 (io), 23 PC16/UDM/T1C4/TX4_/SCL_/SDA_/RX4_/CTS1/PC11 (io), 24 PC17/UDP/RTS1/TX4_/SDA_/SCL_/RX4_/T1ET/PC10 (io), 25 PB12/T1C4_/T2C2N_/PC18/DIO/TX3_/T2C1N_/T3C2_/SDA_/SCL_/T1ET_ (io), 26 PB14/RX3_/PC19/DCK/T2C1_/T3C1_/SCL_/SDA_/RX3_/RX4_ (io), 27 PA8/RTS4 (io), 28 PA9/MISO_/RX4_/T2BK_ (io)

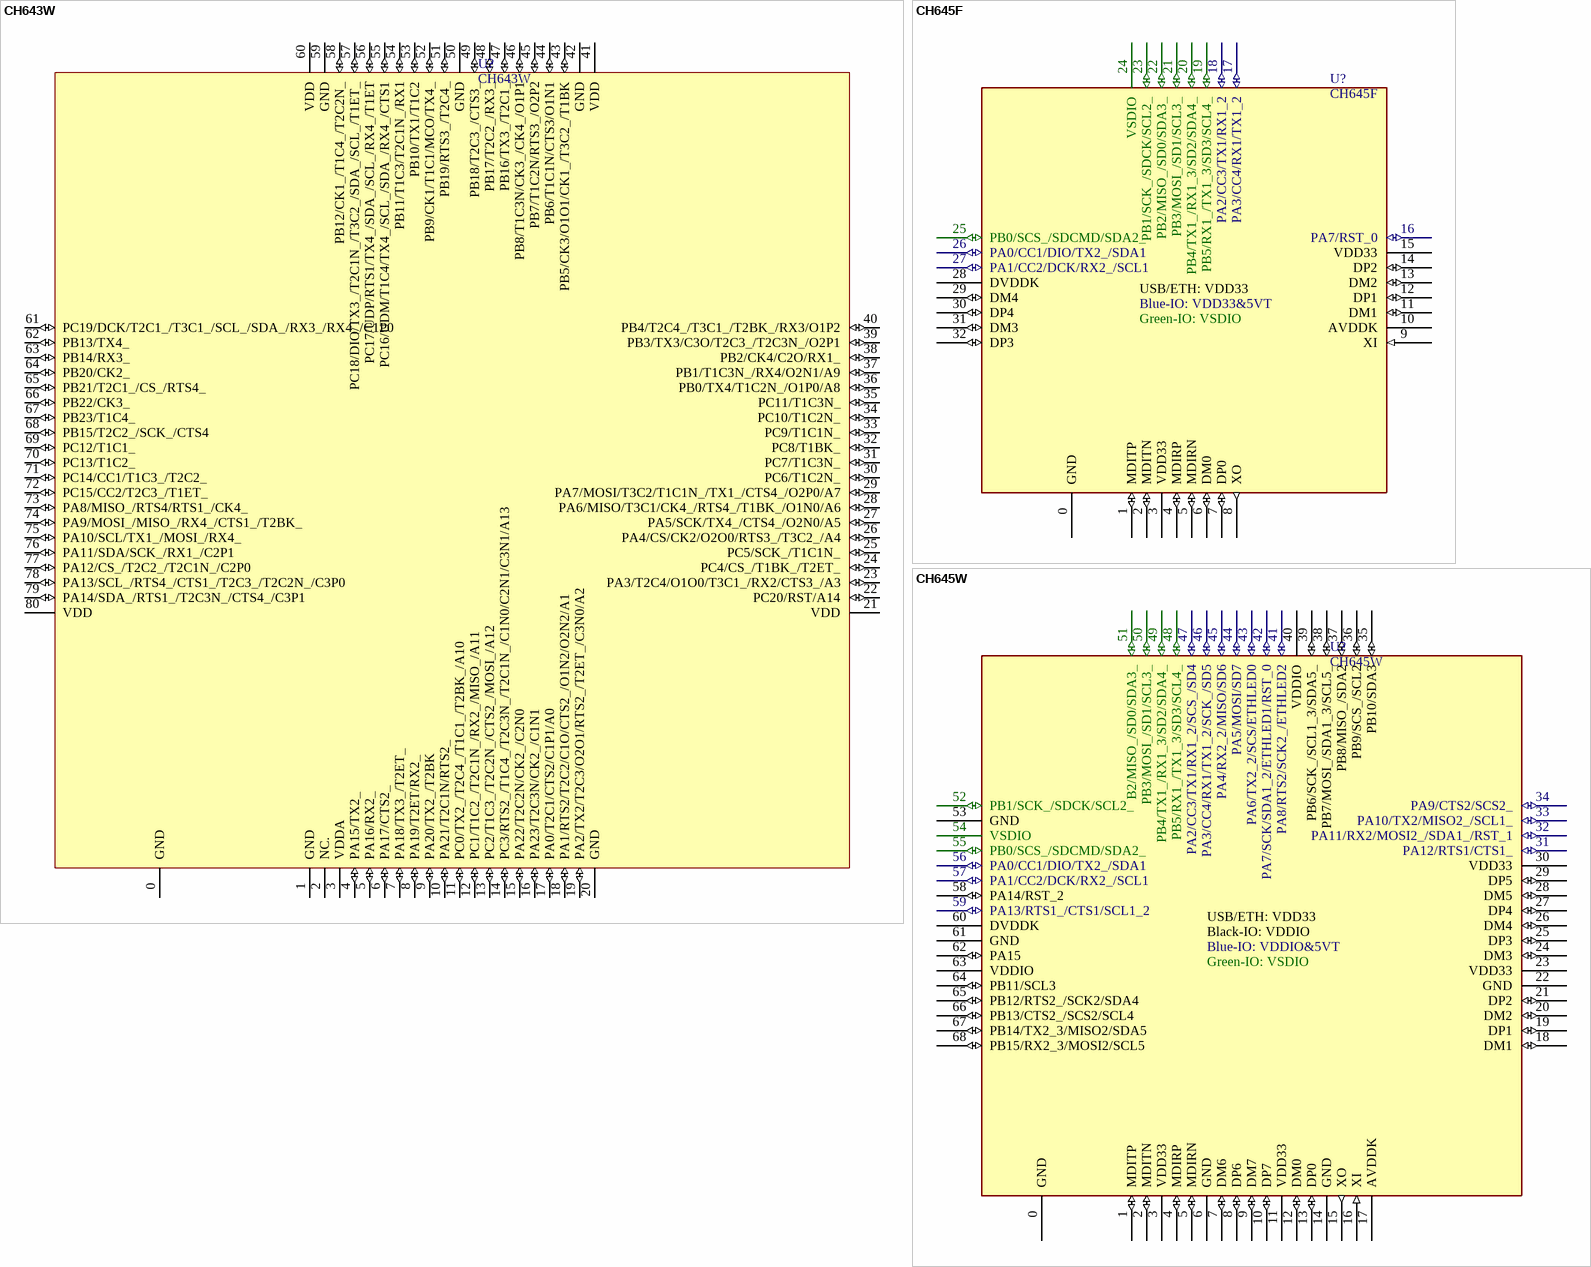
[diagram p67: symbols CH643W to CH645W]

## CH643W
designator U?
RISC-V MCU with USB/RGB/ADC/SPI/I2C/4*UART/PD
footprint QFN80_9X9 (Footprint not found)
pins: 0 GND (power), 1 GND (power), 2 NC., 3 VDDA (power), 4 PA15/TX2_ (io), 5 PA16/RX2_ (io), 6 PA17/CTS2_ (io), 7 PA18/TX3_/T2ET_ (io), 8 PA19/T2ET/RX2_ (io), 9 PA20/TX2_/T2BK (io), 10 PA21/T2C1N/RTS2_ (io), 11 PC0/TX2_/T2C4_/T1C1_/T2BK_/A10 (io), 12 PC1/T1C2_/T2C1N_/RX2_/MISO_/A11 (io), 13 PC2/T1C3_/T2C2N_/CTS2_/MOSI_/A12 (io), 14 PC3/RTS2_/T1C4_/T2C3N_/T2C1N_/C1N0/C2N1/C3N1/A13 (io), 15 PA22/T2C2N/CK2_/C2N0 (io), 16 PA23/T2C3N/CK2_/C1N1 (io), 17 PA0/T2C1/CTS2/C1P1/A0 (io), 18 PA1/RTS2/T2C2/C1O/CTS2_/O1N2/O2N2/A1 (io), 19 PA2/TX2/T2C3/O2O1/RTS2_/T2ET_/C3N0/A2 (io), 20 GND (power), 21 VDD (power), 22 PC20/RST/A14 (io), 23 PA3/T2C4/O1O0/T3C1_/RX2/CTS3_/A3 (io), 24 PC4/CS_/T1BK_/T2ET_ (io), 25 PC5/SCK_/T1C1N_ (io), 26 PA4/CS/CK2/O2O0/RTS3_/T3C2_/A4 (io), 27 PA5/SCK/TX4_/CTS4_/O2N0/A5 (io), 28 PA6/MISO/T3C1/CK4_/RTS4_/T1BK_/O1N0/A6 (io), 29 PA7/MOSI/T3C2/T1C1N_/TX1_/CTS4_/O2P0/A7 (io), 30 PC6/T1C2N_ (io), 31 PC7/T1C3N_ (io), 32 PC8/T1BK_ (io), 33 PC9/T1C1N_ (io), 34 PC10/T1C2N_ (io), 35 PC11/T1C3N_ (io), 36 PB0/TX4/T1C2N_/O1P0/A8 (io), 37 PB1/T1C3N_/RX4/O2N1/A9 (io), 38 PB2/CK4/C2O/RX1_ (io), 39 PB3/TX3/C3O/T2C3_/T2C3N_/O2P1 (io), 40 PB4/T2C4_/T3C1_/T2BK_/RX3/O1P2 (io), 41 VDD (power), 42 GND (power), 43 PB5/CK3/O1O1/CK1_/T3C2_/T1BK (io), 44 PB6/T1C1N/CTS3/O1N1 (io), 45 PB7/T1C2N/RTS3_/O2P2 (io), 46 PB8/T1C3N/CK3_/CK4_/O1P1 (io), 47 PB16/TX3_/T2C1_ (io), 48 PB17/T2C2_/RX3_ (io), 49 PB18/T2C3_/CTS3_ (io), 50 GND (power), 51 PB19/RTS3_/T2C4_ (io), 52 PB9/CK1/T1C1/MCO/TX4_ (io), 53 PB10/TX1/T1C2 (io), 54 PB11/T1C3/T2C1N_/RX1 (io), 55 PC16/UDM/T1C4/TX4_/SCL_/SDA_/RX4_/CTS1 (io), 56 PC17/UDP/RTS1/TX4_/SDA_/SCL_/RX4_/T1ET (io), 57 PC18/DIO/TX3_/T2C1N_/T3C2_/SDA_/SCL_/T1ET_ (io), 58 PB12/CK1_/T1C4_/T2C2N_ (io), 59 GND (power), 60 VDD (power), 61 PC19/DCK/T2C1_/T3C1_/SCL_/SDA_/RX3_/RX4_/C1P0 (io), 62 PB13/TX4_ (io), 63 PB14/RX3_ (io), 64 PB20/CK2_ (io), 65 PB21/T2C1_/CS_/RTS4_ (io), 66 PB22/CK3_ (io), 67 PB23/T1C4_ (io), 68 PB15/T2C2_/SCK_/CTS4 (io), 69 PC12/T1C1_ (io), 70 PC13/T1C2_ (io), 71 PC14/CC1/T1C3_/T2C2_ (io), 72 PC15/CC2/T2C3_/T1ET_ (io), 73 PA8/MISO_/RTS4/RTS1_/CK4_ (io), 74 PA9/MOSI_/MISO_/RX4_/CTS1_/T2BK_ (io), 75 PA10/SCL/TX1_/MOSI_/RX4_ (io), 76 PA11/SDA/SCK_/RX1_/C2P1 (io), 77 PA12/CS_/T2C2_/T2C1N_/C2P0 (io), 78 PA13/SCL_/RTS4_/CTS1_/T2C3_/T2C2N_/C3P0 (io), 79 PA14/SDA_/RTS1_/T2C3N_/CTS4_/C3P1 (io), 80 VDD (power)

## CH645F
designator U?
RISC-V MCU, with 4*USB hub, 4*USB host, 4*I2C, 2*PD, SDIO, ethernet
footprint QFN32_4X4 (Footprint not found)
pins: 0 GND (power), 1 MDITP (io), 2 MDITN (io), 3 VDD33 (power), 4 MDIRP (io), 5 MDIRN (io), 6 DM0 (io), 7 DP0 (io), 8 XO (out), 9 XI (in), 10 AVDDK (power), 11 DM1 (io), 12 DP1 (io), 13 DM2 (io), 14 DP2 (io), 15 VDD33 (power), 16 PA7/RST_0 (io), 17 PA3/CC4/RX1/TX1_2 (io), 18 PA2/CC3/TX1/RX1_2 (io), 19 PB5/RX1_/TX1_3/SD3/SCL4_ (io), 20 PB4/TX1_/RX1_3/SD2/SDA4_ (io), 21 PB3/MOSI_/SD1/SCL3_ (io), 22 PB2/MISO_/SD0/SDA3_ (io), 23 PB1/SCK_/SDCK/SCL2_ (io), 24 VSDIO (power), 25 PB0/SCS_/SDCMD/SDA2_ (io), 26 PA0/CC1/DIO/TX2_/SDA1 (io), 27 PA1/CC2/DCK/RX2_/SCL1 (io), 28 DVDDK (power), 29 DM4 (io), 30 DP4 (io), 31 DM3 (io), 32 DP3 (io)

## CH645W
designator U?
RISC-V MCU for KVM, with 4*USB hub, 4*USB host, 5*I2C, 2*PD, SDIO, ethernet
footprint QFN68_8X8 (Footprint not found)
pins: 0 GND (power), 1 MDITP (io), 2 MDITN (io), 3 VDD33 (power), 4 MDIRP (io), 5 MDIRN (io), 6 GND (power), 7 DM6 (io), 8 DP6 (io), 9 DM7 (io), 10 DP7 (io), 11 VDD33 (power), 12 DM0 (io), 13 DP0 (io), 14 GND (power), 15 XO (out), 16 XI (in), 17 AVDDK (power), 18 DM1 (io), 19 DP1 (io), 20 DM2 (io), 21 DP2 (io), 22 GND (power), 23 VDD33 (power), 24 DM3 (io), 25 DP3 (io), 26 DM4 (io), 27 DP4 (io), 28 DM5 (io), 29 DP5 (io), 30 VDD33 (power), 31 PA12/RTS1/CTS1_ (io), 32 PA11/RX2/MOSI2_/SDA1_/RST_1 (io), 33 PA10/TX2/MISO2_/SCL1_ (io), 34 PA9/CTS2/SCS2_ (io), 35 PB10/SDA3 (io), 36 PB9/SCS_/SCL2 (io), 37 PB8/MISO_/SDA2 (io), 38 PB7/MOSI_/SDA1_3/SCL5_ (io), 39 PB6/SCK_/SCL1_3/SDA5_ (io), 40 VDDIO (power), 41 PA8/RTS2/SCK2_/ETHLED2 (io), 42 PA7/SCK/SDA1_2/ETHLED1/RST_0 (io), 43 PA6/TX2_2/SCS/ETHLED0 (io), 44 PA5/MOSI/SD7 (io), 45 PA4/RX2_2/MISO/SD6 (io), 46 PA3/CC4/RX1/TX1_2/SCK_/SD5 (io), 47 PA2/CC3/TX1/RX1_2/SCS_/SD4 (io), 48 PB5/RX1_/TX1_3/SD3/SCL4_ (io), 49 PB4/TX1_/RX1_3/SD2/SDA4_ (io), 50 PB3/MOSI_/SD1/SCL3_ (io), 51 B2/MISO_/SD0/SDA3_ (io), 52 PB1/SCK_/SDCK/SCL2_ (io), 53 GND (power), 54 VSDIO (power), 55 PB0/SCS_/SDCMD/SDA2_ (io), 56 PA0/CC1/DIO/TX2_/SDA1 (io), 57 PA1/CC2/DCK/RX2_/SCL1 (io), 58 PA14/RST_2 (io), 59 PA13/RTS1_/CTS1/SCL1_2 (io), 60 DVDDK (power), 61 GND (power), 62 PA15 (io), 63 VDDIO (power), 64 PB11/SCL3 (io), 65 PB12/RTS2_/SCK2/SDA4 (io), 66 PB13/CTS2_/SCS2/SCL4 (io), 67 PB14/TX2_3/MISO2/SDA5 (io), 68 PB15/RX2_3/MOSI2/SCL5 (io)

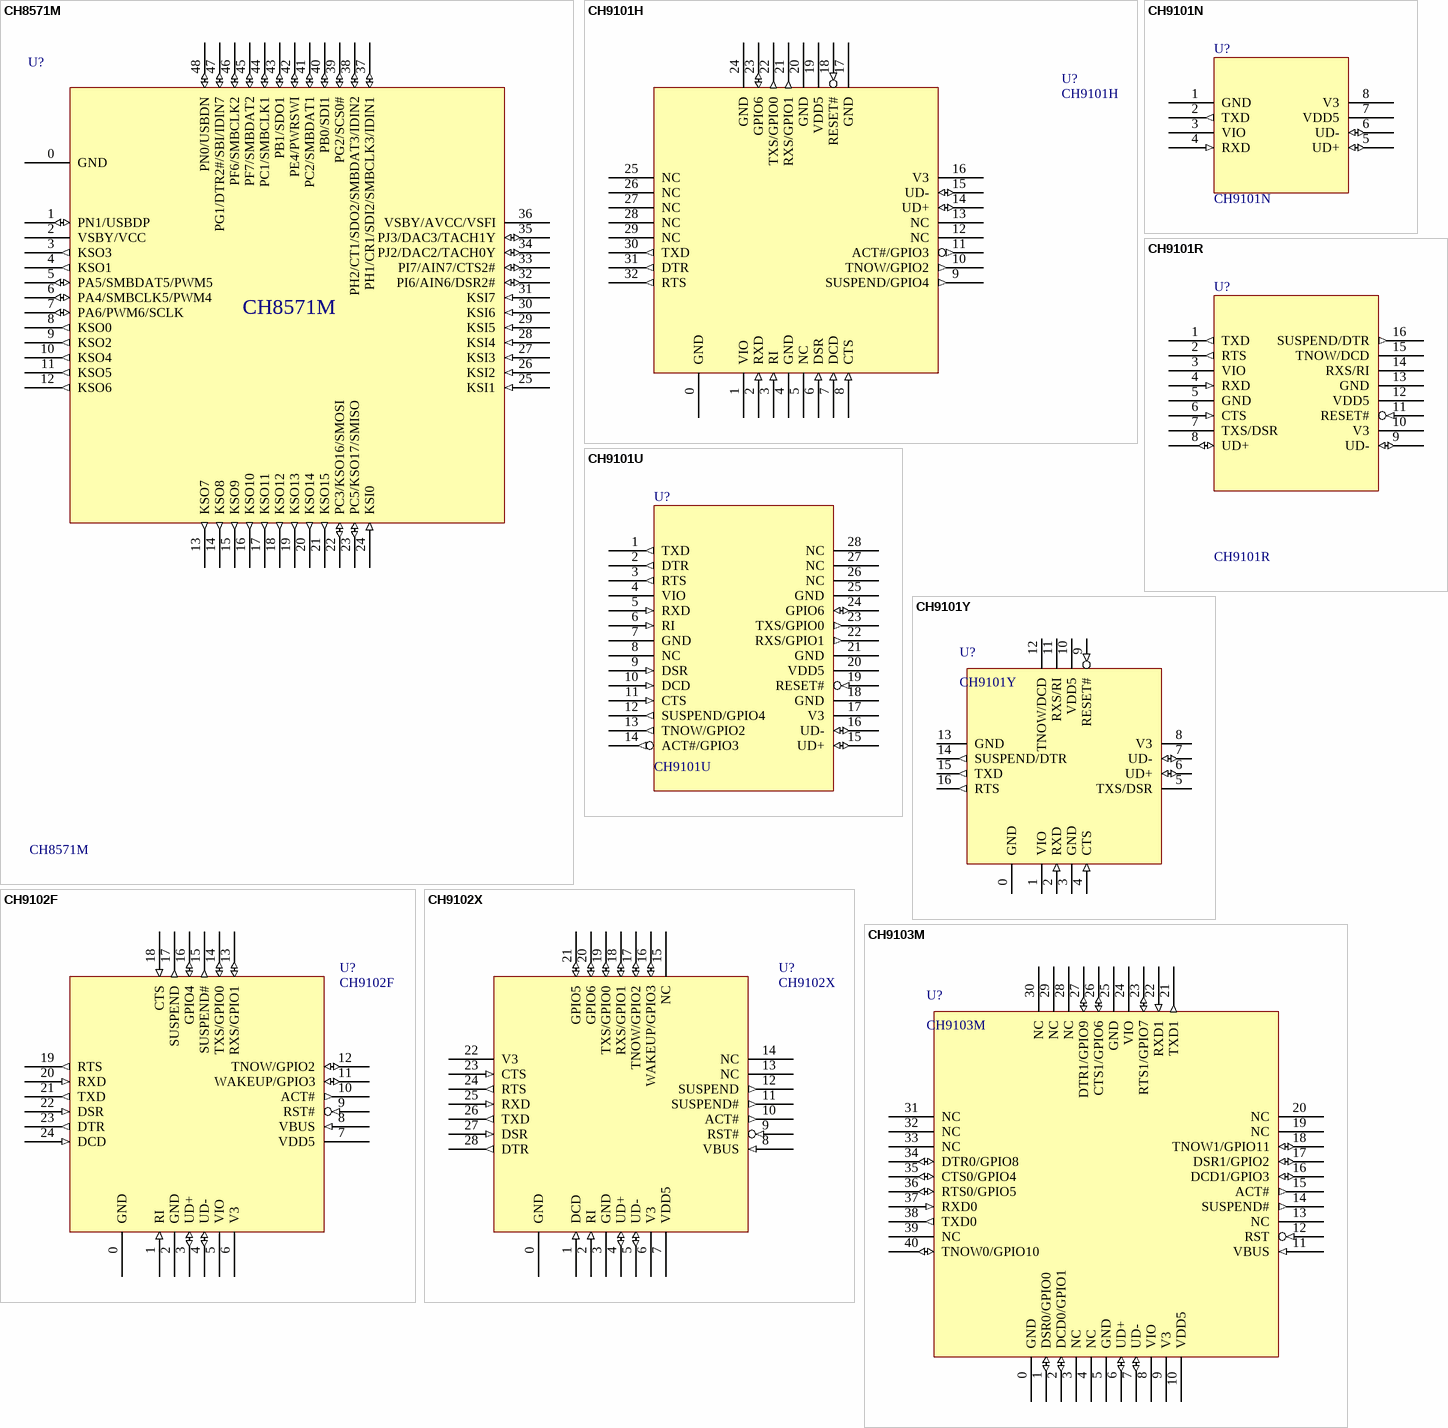
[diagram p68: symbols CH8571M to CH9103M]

## CH8571M
designator U?
RISC-V embedded controller for mobile platforms
footprint QFN48_7X7 (Footprint not found)
pins: 0 GND (power), 1 PN1/USBDP (io), 2 VSBY/VCC (power), 3 KSO3 (out), 4 KSO1 (out), 5 PA5/SMBDAT5/PWM5 (io), 6 PA4/SMBCLK5/PWM4 (io), 7 PA6/PWM6/SCLK (io), 8 KSO0 (out), 9 KSO2 (out), 10 KSO4 (out), 11 KSO5 (out), 12 KSO6 (out), 13 KSO7 (out), 14 KSO8 (out), 15 KSO9 (out), 16 KSO10 (out), 17 KSO11 (out), 18 KSO12 (out), 19 KSO13 (out), 20 KSO14 (out), 21 KSO15 (out), 22 PC3/KSO16/SMOSI (io), 23 PC5/KSO17/SMISO (io), 24 KSI0 (in), 25 KSI1 (in), 26 KSI2 (in), 27 KSI3 (in), 28 KSI4 (in), 29 KSI5 (in), 30 KSI6 (in), 31 KSI7 (in), 32 PI6/AIN6/DSR2# (io), 33 PI7/AIN7/CTS2# (io), 34 PJ2/DAC2/TACH0Y (io), 35 PJ3/DAC3/TACH1Y (io), 36 VSBY/AVCC/VSFI (power), 37 PH1/CR1/SDI2/SMBCLK3/IDIN1 (io), 38 PH2/CT1/SDO2/SMBDAT3/IDIN2 (io), 39 PG2/SCS0# (io), 40 PB0/SDI1 (io), 41 PC2/SMBDAT1 (io), 42 PE4/PWRSWI (io), 43 PB1/SDO1 (io), 44 PC1/SMBCLK1 (io), 45 PF7/SMBDAT2 (io), 46 PF6/SMBCLK2 (io), 47 PG1/DTR2#/SBI/IDIN7 (io), 48 PN0/USBDN (io)

## CH9101H
designator U?
USB to high speed TTL Serial / UART
footprint QFN32_5X5
pins: 0 GND (power), 1 VIO (power), 2 RXD (in), 3 RI (in), 4 GND (power), 5 NC, 6 DSR (in), 7 DCD (in), 8 CTS (in), 9 SUSPEND/GPIO4 (out), 10 TNOW/GPIO2 (out), 11 ACT#/GPIO3 (out), 12 NC, 13 NC, 14 UD+ (io), 15 UD- (io), 16 V3 (power), 17 GND (power), 18 RESET# (in), 19 VDD5 (power), 20 GND (power), 21 RXS/GPIO1 (out), 22 TXS/GPIO0 (out), 23 GPIO6 (io), 24 GND (power), 25 NC, 26 NC, 27 NC, 28 NC, 29 NC, 30 TXD (out), 31 DTR (out), 32 RTS (out)

## CH9101N
designator U?
USB to high speed TTL Serial / UART
footprint SOP8
pins: 1 GND (power), 2 TXD (out), 3 VIO (power), 4 RXD (in), 5 UD+ (io), 6 UD- (io), 7 VDD5 (power), 8 V3 (power)

## CH9101R
designator U?
USB to high speed TTL Serial / UART
footprint QSOP16
pins: 1 TXD (out), 2 RTS (out), 3 VIO (power), 4 RXD (in), 5 GND (power), 6 CTS (in), 7 TXS/DSR, 8 UD+ (io), 9 UD- (io), 10 V3 (power), 11 RESET# (in), 12 VDD5 (power), 13 GND (power), 14 RXS/RI, 15 TNOW/DCD, 16 SUSPEND/DTR (out)

## CH9101U
designator U?
USB to high speed TTL Serial / UART
footprint SSOP28 (Footprint not found)
pins: 1 TXD (out), 2 DTR (out), 3 RTS (out), 4 VIO (power), 5 RXD (in), 6 RI (in), 7 GND (power), 8 NC, 9 DSR (in), 10 DCD (in), 11 CTS (in), 12 SUSPEND/GPIO4 (out), 13 TNOW/GPIO2 (out), 14 ACT#/GPIO3 (out), 15 UD+ (io), 16 UD- (io), 17 V3 (power), 18 GND (power), 19 RESET# (in), 20 VDD5 (power), 21 GND (power), 22 RXS/GPIO1 (out), 23 TXS/GPIO0 (out), 24 GPIO6 (io), 25 GND (power), 26 NC, 27 NC, 28 NC

## CH9101Y
designator U?
USB to high speed TTL Serial / UART
footprint QFN16_4X4
pins: 0 GND (power), 1 VIO (power), 2 RXD (in), 3 GND (power), 4 CTS (in), 5 TXS/DSR, 6 UD+ (io), 7 UD- (io), 8 V3 (power), 9 RESET# (in), 10 VDD5 (power), 11 RXS/RI, 12 TNOW/DCD, 13 GND (power), 14 SUSPEND/DTR (out), 15 TXD (out), 16 RTS (out)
